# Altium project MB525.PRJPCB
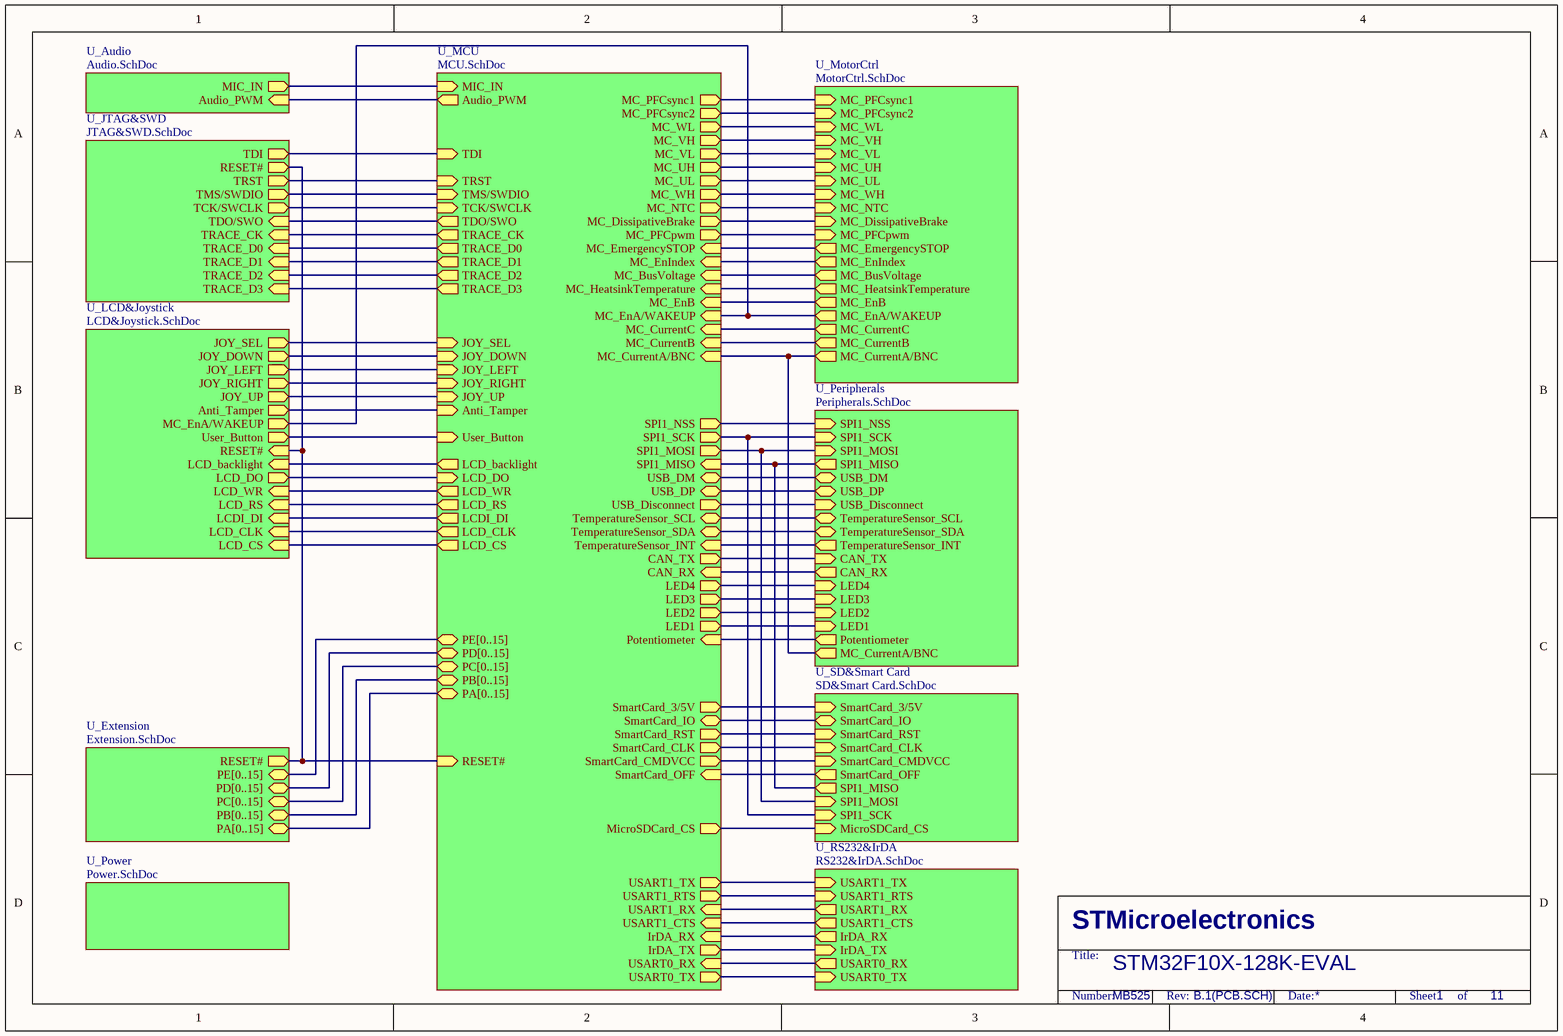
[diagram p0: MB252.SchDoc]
11 sheets, 281 parts. Net scope: hierarchical (ports join the sheet entries above them; power ports are global).
Board file: MB525.PCBDOC
Sheets:
  MB252.SchDoc
    U_MCU = MCU.SchDoc
    U_Audio = Audio.SchDoc
    U_Extension = Extension.SchDoc
    U_JTAG&SWD = JTAG&SWD.SchDoc
    U_LCD&Joystick = LCD&Joystick.SchDoc
    U_MotorCtrl = MotorCtrl.SchDoc
    U_Peripherals = Peripherals.SchDoc
    U_Power = Power.SchDoc
    U_RS232&IrDA = RS232&IrDA.SchDoc
    U_SD&Smart Card = SD&Smart Card.SchDoc

## Sheet MB252.SchDoc
size A4; Revision: B.1(PCB.SCH)

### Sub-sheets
U_Audio = Audio.SchDoc: Audio_PWM (in), MIC_IN (out)
U_Extension = Extension.SchDoc: PA[0..15] (bidir), PB[0..15] (bidir), PC[0..15] (bidir), PD[0..15] (bidir), PE[0..15] (bidir), RESET# (out)
U_JTAG&SWD = JTAG&SWD.SchDoc: TDI (out), RESET# (out), TRACE_D3 (in), TRACE_D2 (in), TRACE_D1 (in), TRACE_D0 (in), TRACE_CK (in), TRST (out), TMS/SWDIO (out), TCK/SWCLK (out), TDO/SWO (in)
U_LCD&Joystick = LCD&Joystick.SchDoc: JOY_SEL (out), JOY_DOWN (out), JOY_LEFT (out), JOY_RIGHT (out), JOY_UP (out), LCD_CS (in), LCD_CLK (in), LCD_DO (out), LCDI_DI (in), LCD_RS (in), LCD_WR (in), RESET# (in), LCD_backlight (in), Anti_Tamper (out), MC_EnA/WAKEUP (out), User_Button (out)
U_MCU = MCU.SchDoc: MC_EnA/WAKEUP (in), MC_EnB (in), JOY_DOWN (in), MC_BusVoltage (in), SPI1_NSS (out), SPI1_SCK (out), SPI1_MISO (in), SPI1_MOSI (out), LCD_backlight (out), USART0_TX (out), USART0_RX (in), USB_DM (bidir), USB_DP (bidir), TMS/SWDIO (in), TCK/SWCLK (in), TDI (in), MC_PFCsync1 (out), MC_PFCpwm (out), TDO/SWO (out), TRST (in), TemperatureSensor_INT (in), TemperatureSensor_SCL (bidir), TemperatureSensor_SDA (bidir), Audio_PWM (out), User_Button (in), SmartCard_IO (bidir), SmartCard_RST (out), SmartCard_CLK (out), LCD_CLK (out), LCD_DO (in), LCDI_DI (out), LCD_CS (out), RESET# (in), LCD_WR (out), MC_EnIndex (in), MC_DissipativeBrake (out), JOY_SEL (in), SmartCard_3/5V (out), MC_NTC (out), USB_Disconnect (out), JOY_UP (in), USART1_RX (in), USART1_TX (out), USART1_RTS (out), USART1_CTS (in), MC_PFCsync2 (out), CAN_TX (out), CAN_RX (in), MC_EmergencySTOP (in), SmartCard_OFF (in), MC_WL (out), MC_VH (out), MC_VL (out), MC_UH (out), MC_UL (out), SmartCard_CMDVCC (out), TRACE_D3 (out), TRACE_D2 (out), TRACE_D1 (out), TRACE_D0 (out), TRACE_CK (out), JOY_LEFT (in), JOY_RIGHT (in), MC_WH (out), LCD_RS (out), Anti_Tamper (in), MicroSDCard_CS (out), IrDA_RX (in), IrDA_TX (out), LED4 (out), LED3 (out), LED1 (out), MIC_IN (in), Potentiometer (in), MC_CurrentC (in), MC_CurrentB (in), MC_CurrentA/BNC (in), MC_HeatsinkTemperature (in), LED2 (out), PA[0..15] (bidir), PB[0..15] (bidir), PC[0..15] (bidir), PD[0..15] (bidir), PE[0..15] (bidir)
U_MotorCtrl = MotorCtrl.SchDoc: MC_EmergencySTOP (out), MC_CurrentA/BNC (out), MC_CurrentB (out), MC_CurrentC (out), MC_PFCsync1 (in), MC_PFCsync2 (in), MC_WL (in), MC_VH (in), MC_VL (in), MC_UH (in), MC_UL (in), MC_WH (in), MC_NTC (in), MC_DissipativeBrake (in), MC_PFCpwm (in), MC_EnA/WAKEUP (out), MC_EnB (out), MC_HeatsinkTemperature (out), MC_BusVoltage (out), MC_EnIndex (out)
U_Peripherals = Peripherals.SchDoc: SPI1_NSS (in), SPI1_SCK (in), SPI1_MISO (out), SPI1_MOSI (in), LED4 (in), LED3 (in), LED1 (in), LED2 (in), USB_DM (bidir), USB_DP (bidir), USB_Disconnect (in), TemperatureSensor_INT (out), TemperatureSensor_SCL (bidir), TemperatureSensor_SDA (bidir), MC_CurrentA/BNC (out), CAN_TX (in), CAN_RX (out), Potentiometer (out)
U_Power = Power.SchDoc: no entries
U_RS232&IrDA = RS232&IrDA.SchDoc: USART1_RX (out), USART1_TX (in), USART1_RTS (in), USART1_CTS (out), USART0_TX (in), USART0_RX (out), IrDA_RX (out), IrDA_TX (in)
U_SD&Smart Card = SD&Smart Card.SchDoc: SmartCard_3/5V (in), SmartCard_IO (bidir), SmartCard_RST (in), SmartCard_CLK (in), SmartCard_OFF (out), SmartCard_CMDVCC (in), SPI1_SCK (in), SPI1_MISO (out), SPI1_MOSI (in), MicroSDCard_CS (in)

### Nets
PA0: sheet U_MCU/MC_EnA/WAKEUP, sheet U_LCD&Joystick/MC_EnA/WAKEUP, sheet U_MotorCtrl/MC_EnA/WAKEUP
PA1: sheet U_MCU/MC_EnB, sheet U_MotorCtrl/MC_EnB
PA2: sheet U_MCU/MC_EnIndex, sheet U_MotorCtrl/MC_EnIndex
PA3: sheet U_MCU/MC_BusVoltage, sheet U_MotorCtrl/MC_BusVoltage
PA4: sheet U_MCU/SPI1_NSS, sheet U_Peripherals/SPI1_NSS
PA5: sheet U_MCU/SPI1_SCK, sheet U_Peripherals/SPI1_SCK, sheet U_SD&Smart Card/SPI1_SCK
PA6: sheet U_MCU/SPI1_MISO, sheet U_Peripherals/SPI1_MISO, sheet U_SD&Smart Card/SPI1_MISO
PA7: sheet U_MCU/SPI1_MOSI, sheet U_Peripherals/SPI1_MOSI, sheet U_SD&Smart Card/SPI1_MOSI
PA8: sheet U_MCU/LCD_backlight, sheet U_LCD&Joystick/LCD_backlight
PA9: sheet U_MCU/USART0_TX, sheet U_RS232&IrDA/USART0_TX
PA10: sheet U_MCU/USART0_RX, sheet U_RS232&IrDA/USART0_RX
PA11: sheet U_MCU/USB_DM, sheet U_Peripherals/USB_DM
PA12: sheet U_MCU/USB_DP, sheet U_Peripherals/USB_DP
PA13: sheet U_MCU/TMS/SWDIO, sheet U_JTAG&SWD/TMS/SWDIO
PA14: sheet U_MCU/TCK/SWCLK, sheet U_JTAG&SWD/TCK/SWCLK
PA15: sheet U_MCU/TDI, sheet U_JTAG&SWD/TDI
PB0: sheet U_MCU/MC_PFCsync1, sheet U_MotorCtrl/MC_PFCsync1
PB1: sheet U_MCU/MC_PFCpwm, sheet U_MotorCtrl/MC_PFCpwm
PB2: sheet U_MCU/LCD_CS, sheet U_LCD&Joystick/LCD_CS
PB3: sheet U_MCU/TDO/SWO, sheet U_JTAG&SWD/TDO/SWO
PB4: sheet U_MCU/TRST, sheet U_JTAG&SWD/TRST
PB5: sheet U_MCU/TemperatureSensor_INT, sheet U_Peripherals/TemperatureSensor_INT
PB6: sheet U_MCU/TemperatureSensor_SCL, sheet U_Peripherals/TemperatureSensor_SCL
PB7: sheet U_MCU/TemperatureSensor_SDA, sheet U_Peripherals/TemperatureSensor_SDA
PB8: sheet U_MCU/Audio_PWM, sheet U_Audio/Audio_PWM
PB9: sheet U_MCU/User_Button, sheet U_LCD&Joystick/User_Button
PB10: sheet U_MCU/SmartCard_IO, sheet U_SD&Smart Card/SmartCard_IO
PB11: sheet U_MCU/SmartCard_RST, sheet U_SD&Smart Card/SmartCard_RST
PB12: sheet U_MCU/SmartCard_CLK, sheet U_SD&Smart Card/SmartCard_CLK
PB13: sheet U_MCU/LCD_CLK, sheet U_LCD&Joystick/LCD_CLK
PB14: sheet U_MCU/LCD_DO, sheet U_LCD&Joystick/LCD_DO
PB15: sheet U_MCU/LCDI_DI, sheet U_LCD&Joystick/LCDI_DI
PC0: sheet U_MCU/MC_HeatsinkTemperature, sheet U_MotorCtrl/MC_HeatsinkTemperature
PC1: sheet U_MCU/MC_CurrentA/BNC, sheet U_MotorCtrl/MC_CurrentA/BNC, sheet U_Peripherals/MC_CurrentA/BNC
PC2: sheet U_MCU/MC_CurrentB, sheet U_MotorCtrl/MC_CurrentB
PC3: sheet U_MCU/MC_CurrentC, sheet U_MotorCtrl/MC_CurrentC
PC4: sheet U_MCU/Potentiometer, sheet U_Peripherals/Potentiometer
PC5: sheet U_MCU/MIC_IN, sheet U_Audio/MIC_IN
PC6: sheet U_MCU/LED1, sheet U_Peripherals/LED1
PC7: sheet U_MCU/LED2, sheet U_Peripherals/LED2
PC8: sheet U_MCU/LED3, sheet U_Peripherals/LED3
PC9: sheet U_MCU/LED4, sheet U_Peripherals/LED4
PC10: sheet U_MCU/IrDA_TX, sheet U_RS232&IrDA/IrDA_TX
PC11: sheet U_MCU/IrDA_RX, sheet U_RS232&IrDA/IrDA_RX
PC12: sheet U_MCU/MicroSDCard_CS, sheet U_SD&Smart Card/MicroSDCard_CS
PC13: sheet U_MCU/Anti_Tamper, sheet U_LCD&Joystick/Anti_Tamper
PD0: sheet U_MCU/CAN_RX, sheet U_Peripherals/CAN_RX
PD1: sheet U_MCU/CAN_TX, sheet U_Peripherals/CAN_TX
PD2: sheet U_MCU/MC_PFCsync2, sheet U_MotorCtrl/MC_PFCsync2
PD3: sheet U_MCU/USART1_CTS, sheet U_RS232&IrDA/USART1_CTS
PD4: sheet U_MCU/USART1_RTS, sheet U_RS232&IrDA/USART1_RTS
PD5: sheet U_MCU/USART1_TX, sheet U_RS232&IrDA/USART1_TX
PD6: sheet U_MCU/USART1_RX, sheet U_RS232&IrDA/USART1_RX
PD7: sheet U_MCU/LCD_RS, sheet U_LCD&Joystick/LCD_RS
PD8: sheet U_MCU/JOY_UP, sheet U_LCD&Joystick/JOY_UP
PD9: sheet U_MCU/USB_Disconnect, sheet U_Peripherals/USB_Disconnect
PD10: sheet U_MCU/MC_NTC, sheet U_MotorCtrl/MC_NTC
PD11: sheet U_MCU/SmartCard_3/5V, sheet U_SD&Smart Card/SmartCard_3/5V
PD12: sheet U_MCU/JOY_SEL, sheet U_LCD&Joystick/JOY_SEL
PD13: sheet U_MCU/MC_DissipativeBrake, sheet U_MotorCtrl/MC_DissipativeBrake
PD14: sheet U_MCU/JOY_DOWN, sheet U_LCD&Joystick/JOY_DOWN
PD15: sheet U_MCU/LCD_WR, sheet U_LCD&Joystick/LCD_WR
PE0: sheet U_MCU/JOY_RIGHT, sheet U_LCD&Joystick/JOY_RIGHT
PE1: sheet U_MCU/JOY_LEFT, sheet U_LCD&Joystick/JOY_LEFT
PE2: sheet U_MCU/TRACE_CK, sheet U_JTAG&SWD/TRACE_CK
PE3: sheet U_MCU/TRACE_D0, sheet U_JTAG&SWD/TRACE_D0
PE4: sheet U_MCU/TRACE_D1, sheet U_JTAG&SWD/TRACE_D1
PE5: sheet U_MCU/TRACE_D2, sheet U_JTAG&SWD/TRACE_D2
PE6: sheet U_MCU/TRACE_D3, sheet U_JTAG&SWD/TRACE_D3
PE7: sheet U_MCU/SmartCard_CMDVCC, sheet U_SD&Smart Card/SmartCard_CMDVCC
PE8: sheet U_MCU/MC_UL, sheet U_MotorCtrl/MC_UL
PE9: sheet U_MCU/MC_UH, sheet U_MotorCtrl/MC_UH
PE10: sheet U_MCU/MC_VL, sheet U_MotorCtrl/MC_VL
PE11: sheet U_MCU/MC_VH, sheet U_MotorCtrl/MC_VH
PE12: sheet U_MCU/MC_WL, sheet U_MotorCtrl/MC_WL
PE13: sheet U_MCU/MC_WH, sheet U_MotorCtrl/MC_WH
PE14: sheet U_MCU/SmartCard_OFF, sheet U_SD&Smart Card/SmartCard_OFF
PE15: sheet U_MCU/MC_EmergencySTOP, sheet U_MotorCtrl/MC_EmergencySTOP
RESET#: sheet U_MCU/RESET#, sheet U_Extension/RESET#, sheet U_JTAG&SWD/RESET#, sheet U_LCD&Joystick/RESET#

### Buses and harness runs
bus sheet U_Extension/PA[0..15] = sheet U_MCU/PA[0..15]
bus sheet U_Extension/PB[0..15] = sheet U_MCU/PB[0..15]
bus sheet U_Extension/PC[0..15] = sheet U_MCU/PC[0..15]
bus sheet U_Extension/PD[0..15] = sheet U_MCU/PD[0..15]
bus sheet U_Extension/PE[0..15] = sheet U_MCU/PE[0..15]

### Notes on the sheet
- STM32F10X-128K-EVAL
- MB525
- 1
- 11

## Sheet MCU.SchDoc
size A4; Revision: B.1(PCB.SCH)
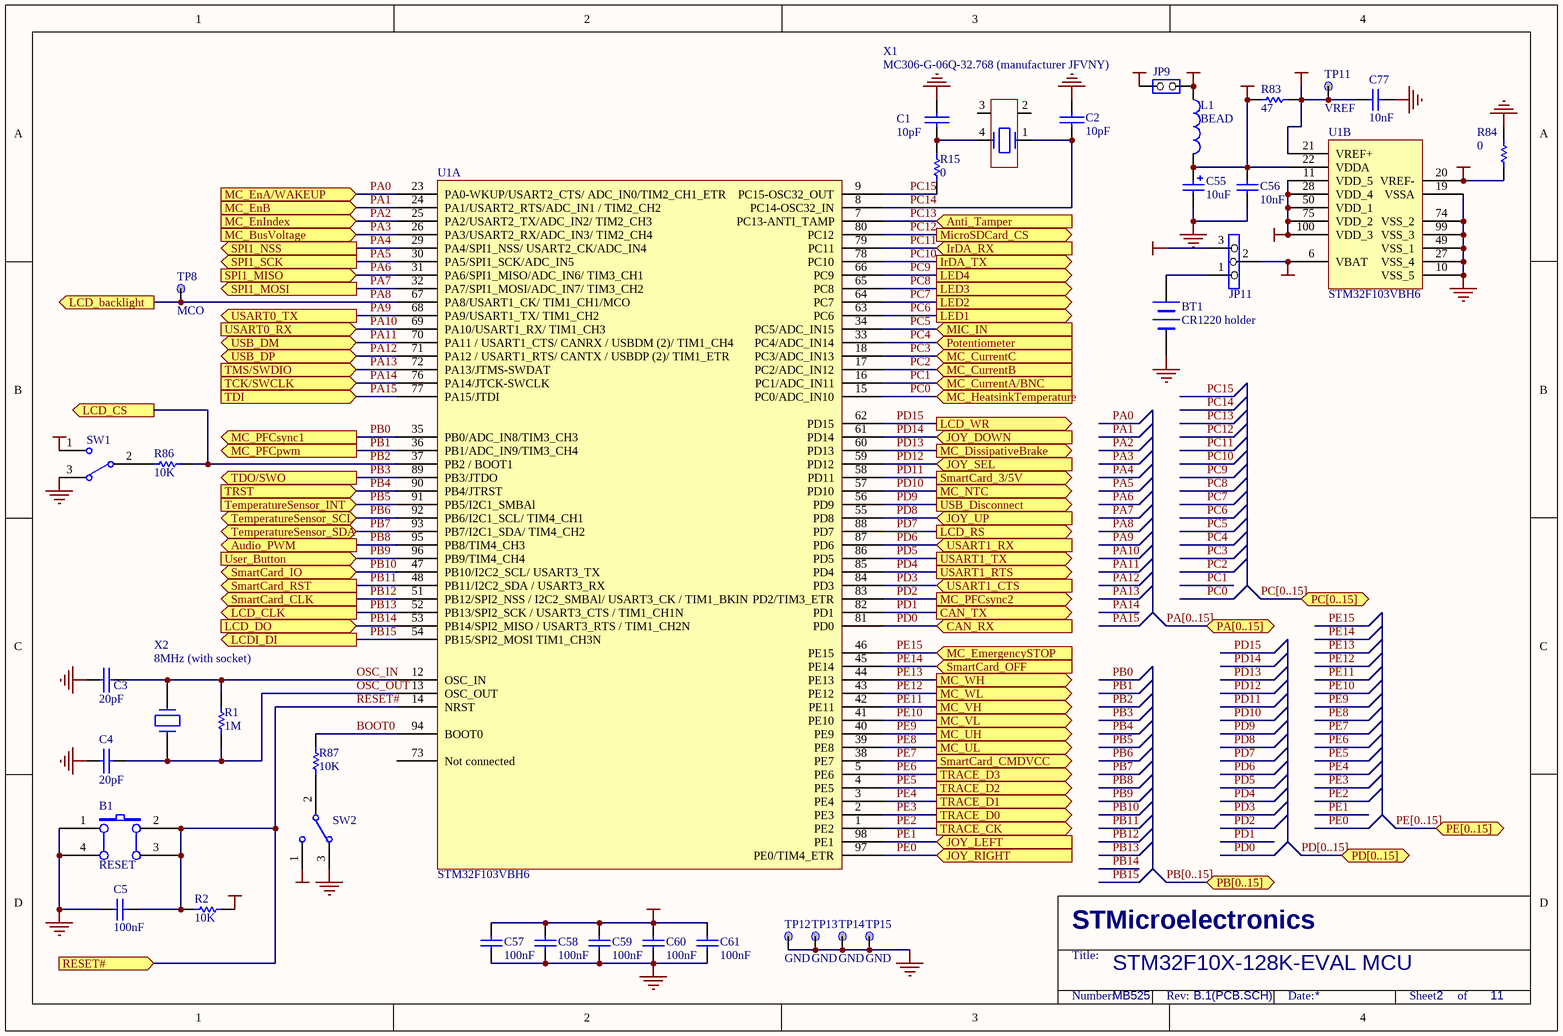
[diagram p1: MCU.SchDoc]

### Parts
B1  RESET  [PB10]
BT1  CR1220 holder  [BATT]
C1  10pF  [0603]
C2  10pF  [0603]
C3  20pF  [0603]
C4  20pF  [0603]
C5  100nF  [0603P]
C55  10uF  [TAN-B]
C56  10nF  [0603]
C57  100nF  [0603P]
C58  100nF  [0603P]
C59  100nF  [0603P]
C60  100nF  [0603P]
C61  100nF  [0603P]
C77  10nF  [0603]
JP9  (no value)  [SIP2]
JP11  (no value)  [SIP3]
L1  BEAD  [0603]
R1  1M  [0603]
R2  10K  [0603]
R15  0  [0805]
R83  47  [0805]
R84  0  [0805]
R86  10K  [0603]
R87  10K  [0603]
SW1  (no value)  [SIP3]
SW2  (no value)  [SIP3]
TP8  MCO  [TP]
TP11  VREF  [TP]
TP12  GND  [TP]
TP13  GND  [TP]
TP14  GND  [TP]
TP15  GND  [TP]
U1  STM32F103VBH6  (parts A,B of 2)
X1  MC306-G-06Q-32.768 (manufacturer JFVNY)  [SM8]
X2  8MHz (with socket)  [XTAL1]

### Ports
Anti_Tamper (in), Audio_PWM (out), CAN_RX (in), CAN_TX (out), IrDA_RX (in), IrDA_TX (out), JOY_DOWN (in), JOY_LEFT (in), JOY_RIGHT (in), JOY_SEL (in), JOY_UP (in), LCD_backlight (out), LCD_CLK (out), LCD_CS (out), LCD_DO (in), LCD_RS (out), LCD_WR (out), LCDI_DI (out), LED1 (out), LED2 (out), LED3 (out), LED4 (out), MC_BusVoltage (in), MC_CurrentA/BNC (in), MC_CurrentB (in), MC_CurrentC (in), MC_DissipativeBrake (out), MC_EmergencySTOP (in), MC_EnA/WAKEUP (in), MC_EnB (in), MC_EnIndex (in), MC_HeatsinkTemperature (in), MC_NTC (out), MC_PFCpwm (out), MC_PFCsync1 (out), MC_PFCsync2 (out), MC_UH (out), MC_UL (out), MC_VH (out), MC_VL (out), MC_WH (out), MC_WL (out), MIC_IN (in), MicroSDCard_CS (out), PA[0..15] (bidir), PB[0..15] (bidir), PC[0..15] (bidir), PD[0..15] (bidir), PE[0..15] (bidir), Potentiometer (in), RESET# (in), SmartCard_3/5V (out), SmartCard_CLK (out), SmartCard_CMDVCC (out), SmartCard_IO (bidir), SmartCard_OFF (in), SmartCard_RST (out), SPI1_MISO (in), SPI1_MOSI (out), SPI1_NSS (out), SPI1_SCK (out), TCK/SWCLK (in), TDI (in), TDO/SWO (out), TemperatureSensor_INT (in), TemperatureSensor_SCL (bidir), TemperatureSensor_SDA (bidir), TMS/SWDIO (in), TRACE_CK (out), TRACE_D0 (out), TRACE_D1 (out), TRACE_D2 (out), TRACE_D3 (out), TRST (in), USART0_RX (in), USART0_TX (out), USART1_CTS (in), USART1_RTS (out), USART1_RX (in), USART1_TX (out), USB_Disconnect (out), USB_DM (bidir), USB_DP (bidir), User_Button (in)

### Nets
+3V3: JP9.1(COMMON) JP11.3 R2.2 SW1.1 SW2.1
GND: B1.1(A0) B1.4(A1) BT1.2(-) C1.2 C2.2 C3.2 C4.2 C5.1 C55.2 C56.2 C57.2 C58.2 C59.2 C60.2 C61.2 C77.2 R84.1 SW1.3 SW2.3 TP12.1 TP13.1 TP14.1 TP15.1 U1.10(VSS_5) U1.19(VSSA) U1.27(VSS_4) U1.49(VSS_1) U1.74(VSS_2) U1.99(VSS_3)
Vbat: JP11.2 U1.6(VBAT)
VDD: C57.1 C58.1 C59.1 C60.1 C61.1 JP9.2(NO) L1.1 U1.11(VDD_5) U1.28(VDD_4) U1.50(VDD_1) U1.75(VDD_2) U1.100(VDD_3)
VDDA: C55.1 C56.1 L1.2 R83.2 U1.22(VDDA)
VREF+: C77.1 R83.1 TP11.1 U1.21(VREF+)
VREF-: R84.2 U1.20(VREF-)
BOOT0: R87.1 U1.94(BOOT0)
OSC_IN: C3.1 R1.2 U1.12(OSC_IN) X2.2
OSC_OUT: C4.1 R1.1 U1.13(OSC_OUT) X2.1
PA0: U1.23(PA0-WKUP/USART2_CTS/
ADC_IN0/TIM2_CH1_ETR) ; port MC_EnA/WAKEUP
PA1: U1.24(PA1/USART2_RTS/ADC_IN1
/
TIM2_CH2) ; port MC_EnB
PA2: U1.25(PA2/USART2_TX/ADC_IN2/
TIM2_CH3) ; port MC_EnIndex
PA3: U1.26(PA3/USART2_RX/ADC_IN3/
TIM2_CH4) ; port MC_BusVoltage
PA4: U1.29(PA4/SPI1_NSS/
USART2_CK/ADC_IN4) ; port SPI1_NSS
PA5: U1.30(PA5/SPI1_SCK/ADC_IN5) ; port SPI1_SCK
PA6: U1.31(PA6/SPI1_MISO/ADC_IN6/
TIM3_CH1) ; port SPI1_MISO
PA7: U1.32(PA7/SPI1_MOSI/ADC_IN7/
TIM3_CH2) ; port SPI1_MOSI
PA8: TP8.1 U1.67(PA8/USART1_CK/
TIM1_CH1/MCO) ; port LCD_backlight
PA9: U1.68(PA9/USART1_TX/
TIM1_CH2) ; port USART0_TX
PA10: U1.69(PA10/USART1_RX/
TIM1_CH3) ; port USART0_RX
PA11: U1.70(PA11_/_USART1_CTS/
CANRX_/_USBDM_(2)/
TIM1_CH4) ; port USB_DM
PA12: U1.71(PA12_/_USART1_RTS/
CANTX_/_USBDP_(2)/
TIM1_ETR) ; port USB_DP
PA13: U1.72(PA13/JTMS-SWDAT) ; port TMS/SWDIO
PA14: U1.76(PA14/JTCK-SWCLK) ; port TCK/SWCLK
PA15: U1.77(PA15/JTDI) ; port TDI
PB0: U1.35(PB0/ADC_IN8/TIM3_CH3) ; port MC_PFCsync1
PB1: U1.36(PB1/ADC_IN9/TIM3_CH4) ; port MC_PFCpwm
PB2: R86.1 U1.37(PB2_/_BOOT1) ; port LCD_CS
PB3: U1.89(PB3/JTDO) ; port TDO/SWO
PB4: U1.90(PB4/JTRST) ; port TRST
PB5: U1.91(PB5/I2C1_SMBAl) ; port TemperatureSensor_INT
PB6: U1.92(PB6/I2C1_SCL/
TIM4_CH1) ; port TemperatureSensor_SCL
PB7: U1.93(PB7/I2C1_SDA/
TIM4_CH2) ; port TemperatureSensor_SDA
PB8: U1.95(PB8/TIM4_CH3) ; port Audio_PWM
PB9: U1.96(PB9/TIM4_CH4) ; port User_Button
PB10: U1.47(PB10/I2C2_SCL/
USART3_TX) ; port SmartCard_IO
PB11: U1.48(PB11/I2C2_SDA_/
USART3_RX) ; port SmartCard_RST
PB12: U1.51(PB12/SPI2_NSS_/
I2C2_SMBAl/
USART3_CK_/
TIM1_BKIN) ; port SmartCard_CLK
PB13: U1.52(PB13/SPI2_SCK_/
USART3_CTS_/
TIM1_CH1N) ; port LCD_CLK
PB14: U1.53(PB14/SPI2_MISO_/
USART3_RTS_/
TIM1_CH2N) ; port LCD_DO
PB15: U1.54(PB15/SPI2_MOSI
TIM1_CH3N) ; port LCDI_DI
PC0: U1.15(PC0/ADC_IN10) ; port MC_HeatsinkTemperature
PC1: U1.16(PC1/ADC_IN11) ; port MC_CurrentA/BNC
PC2: U1.17(PC2/ADC_IN12) ; port MC_CurrentB
PC3: U1.18(PC3/ADC_IN13) ; port MC_CurrentC
PC4: U1.33(PC4/ADC_IN14) ; port Potentiometer
PC5: U1.34(PC5/ADC_IN15) ; port MIC_IN
PC6: U1.63(PC6) ; port LED1
PC7: U1.64(PC7) ; port LED2
PC8: U1.65(PC8) ; port LED3
PC9: U1.66(PC9) ; port LED4
PC10: U1.78(PC10) ; port IrDA_TX
PC11: U1.79(PC11) ; port IrDA_RX
PC12: U1.80(PC12) ; port MicroSDCard_CS
PC13: U1.7(PC13-ANTI_TAMP) ; port Anti_Tamper
PC14: C2.1 U1.8(PC14-OSC32_IN) X1.1
PC15: R15.2 U1.9(PC15-OSC32_OUT)
PD0: U1.81(PD0) ; port CAN_RX
PD1: U1.82(PD1) ; port CAN_TX
PD2: U1.83(PD2/TIM3_ETR) ; port MC_PFCsync2
PD3: U1.84(PD3) ; port USART1_CTS
PD4: U1.85(PD4) ; port USART1_RTS
PD5: U1.86(PD5) ; port USART1_TX
PD6: U1.87(PD6) ; port USART1_RX
PD7: U1.88(PD7) ; port LCD_RS
PD8: U1.55(PD8) ; port JOY_UP
PD9: U1.56(PD9) ; port USB_Disconnect
PD10: U1.57(PD10) ; port MC_NTC
PD11: U1.58(PD11) ; port SmartCard_3/5V
PD12: U1.59(PD12) ; port JOY_SEL
PD13: U1.60(PD13) ; port MC_DissipativeBrake
PD14: U1.61(PD14) ; port JOY_DOWN
PD15: U1.62(PD15) ; port LCD_WR
PE0: U1.97(PE0/TIM4_ETR) ; port JOY_RIGHT
PE1: U1.98(PE1) ; port JOY_LEFT
PE2: U1.1(PE2) ; port TRACE_CK
PE3: U1.2(PE3) ; port TRACE_D0
PE4: U1.3(PE4) ; port TRACE_D1
PE5: U1.4(PE5) ; port TRACE_D2
PE6: U1.5(PE6) ; port TRACE_D3
PE7: U1.38(PE7) ; port SmartCard_CMDVCC
PE8: U1.39(PE8) ; port MC_UL
PE9: U1.40(PE9) ; port MC_UH
PE10: U1.41(PE10) ; port MC_VL
PE11: U1.42(PE11) ; port MC_VH
PE12: U1.43(PE12) ; port MC_WL
PE13: U1.44(PE13) ; port MC_WH
PE14: U1.45(PE14) ; port SmartCard_OFF
PE15: U1.46(PE15) ; port MC_EmergencySTOP
RESET#: B1.2(B0) B1.3(B1) C5.2 R2.1 U1.14(NRST) ; port RESET#
NetBT1_1: BT1.1(+) JP11.1
NetC1_1: C1.1 R15.1 X1.4
NetR86_2: R86.2 SW1.2
NetR87_2: R87.2 SW2.2

Not connected (* = marked no-connect by the designer): U1 73(Not_connected); X1 2 3

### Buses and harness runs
bus PA[0..15] = port PA[0..15]
bus PB[0..15] = port PB[0..15]
bus PC[0..15] = port PC[0..15]
bus PD[0..15] = port PD[0..15]
bus PE[0..15] = port PE[0..15]

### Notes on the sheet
- STM32F10X-128K-EVAL MCU
- MB525
- 2
- 11

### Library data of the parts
B1 = SW PUSHBUTTON: SE PUSHBUTTON
BT1 = BATTERY
C1-C4 C57-C61 = CAP: Capacitor
C5 = CAP: Capacitor; Value: 100pF
C55 = Cap Pol1: Polarized Capacitor (Radial)
C56 C77 = Cap: Capacitor
JP9 = JP2
JP11 = Jumper3
L1 = Inductor: Value: 100uH
R1 R15 R83 R84 = Res1: Resistor; Value: 1K
R2 R86 R87 = res1: Resistor; Value: 1K
SW1 SW2 = SW-SPDT: SPDT Subminiature Toggle Switch, Right Angle Mounting, Vertical Actuation; Revision 1: Jul-2002: Re-released for DXP Platform.; Revision 2: 17-Dec-2003: Schematic revised, PCB Footprint replaced.
TP8 TP11-TP15 = TP
X1 = MC306
X2 = CRYSTAL

## Sheet Audio.SchDoc
size A4; Revision: B.1(PCB.SCH)
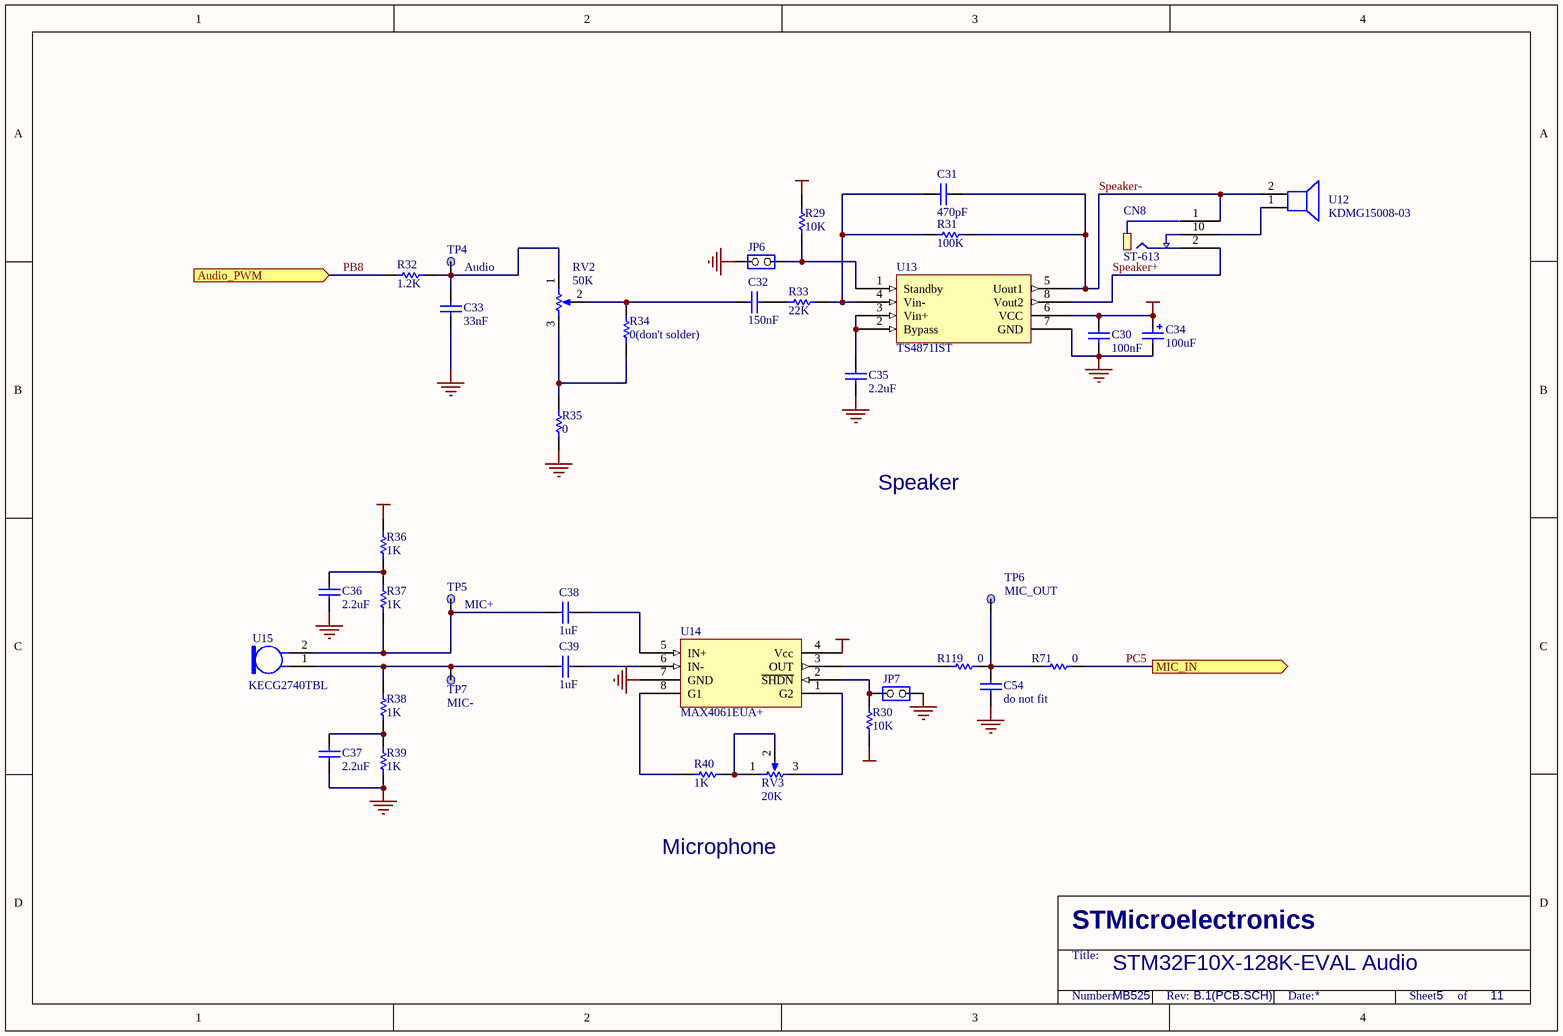
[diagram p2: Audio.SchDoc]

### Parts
C30  100nF  [0603P]
C31  470pF  [0603]
C32  150nF  [0603]
C33  33nF  [0603]
C34  100uF  [TAN-B]
C35  2.2uF  [0805]
C36  2.2uF  [0805]
C37  2.2uF  [0805]
C38  1uF  [0603]
C39  1uF  [0603]
C54  do not fit  [0603]
CN8  ST-613  [PJST-613]
JP6  (no value)  [SIP2]
JP7  (no value)  [SIP2]
R29  10K  [0603]
R30  10K  [0603]
R31  100K  [0603]
R32  1.2K  [0603]
R33  22K  [0603]
R34  0(don't solder)  [0603]
R35  0  [0603]
R36  1K  [0603]
R37  1K  [0603]
R38  1K  [0603]
R39  1K  [0603]
R40  1K  [0603]
R71  0  [0805]
R119  0  [0603]
RV2  50K  [3314-J]
RV3  20K  [3314-J]
TP4  Audio  [TP]
TP5  MIC+  [TP]
TP6  MIC_OUT  [TP]
TP7  MIC-  [TP]
U12  KDMG15008-03  [KS1508]
U13  TS4871IST  [TSSOP8]
U14  MAX4061EUA+  [tssop8]
U15  KECG2740TBL  [KEC2740]

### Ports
Audio_PWM (in), MIC_IN (out)

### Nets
+3V3: C30.2 C34.1 R29.2 R30.1 R36.2 U13.6(VCC) U14.4(Vcc)
GND: C30.1 C33.1 C34.2 C35.2 C36.2 C37.2 C54.2 JP6.2(NO) JP7.2(NO) R35.1 R39.1 U13.7(GND) U14.7(GND)
PB8: R32.1 ; port Audio_PWM
PC5: R71.1 ; port MIC_IN
Speaker+: CN8.2 U13.8(Vout2)
Speaker-: C31.2 CN8.1 R31.2 U12.2(--) U13.5(Uout1)
NetC31_1: C31.1 R31.1 R33.2 U13.4(Vin-)
NetC32_1: C32.1 R34.2 RV2.2(TAP)
NetC32_2: C32.2 R33.1
NetC33_2: C33.2 R32.2 RV2.1(BOT) TP4.1
NetC35_1: C35.1 U13.2(Bypass) U13.3(Vin+)
NetC36_1: C36.1 R36.1 R37.1
NetC37_1: C37.1 R38.1 R39.2
NetC38_1: C38.1 R37.2 TP5.1 U15.2
NetC38_2: C38.2 U14.5(IN+)
NetC39_1: C39.1 R38.2 TP7.1 U15.1
NetC39_2: C39.2 U14.6(IN-)
NetC54_1: C54.1 R71.2 R119.1 TP6.1
NetCN8_10: CN8.10 U12.1(+)
NetJP6_1: JP6.1(COMMON) R29.1 U13.1(Standby)
NetJP7_1: JP7.1(COMMON) R30.2 U14.2(~{SHDN})
NetR34_1: R34.1 R35.2 RV2.3(TOP)
NetR40_1: R40.1 RV3.1(BOT) RV3.2(TAP)
NetR40_2: R40.2 U14.8(G1)
NetR119_2: R119.2 U14.3(OUT)
NetRV3_3: RV3.3(TOP) U14.1(G2)

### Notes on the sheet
- Speaker
- Microphone
- STM32F10X-128K-EVAL Audio
- MB525
- 5
- 11

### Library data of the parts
C30-C33 C35-C39 = CAP: Capacitor; Value: 100pF
C34 = Cap Pol1: Polarized Capacitor (Radial); Value: 100pF
C54 = CAP: Capacitor; Value: 100nF
JP6 JP7 = JP2
R29-R35 R71 R119 = Res1: Resistor; Value: 1K
R36-R40 = Res1: Resistor
RV2 RV3 = RV
TP4-TP7 = TP
U12 = Speaker: Loudspeaker
U15 = Mic2: Microphone

## Sheet Extension.SchDoc
size A4; Revision: B.1(PCB.SCH)
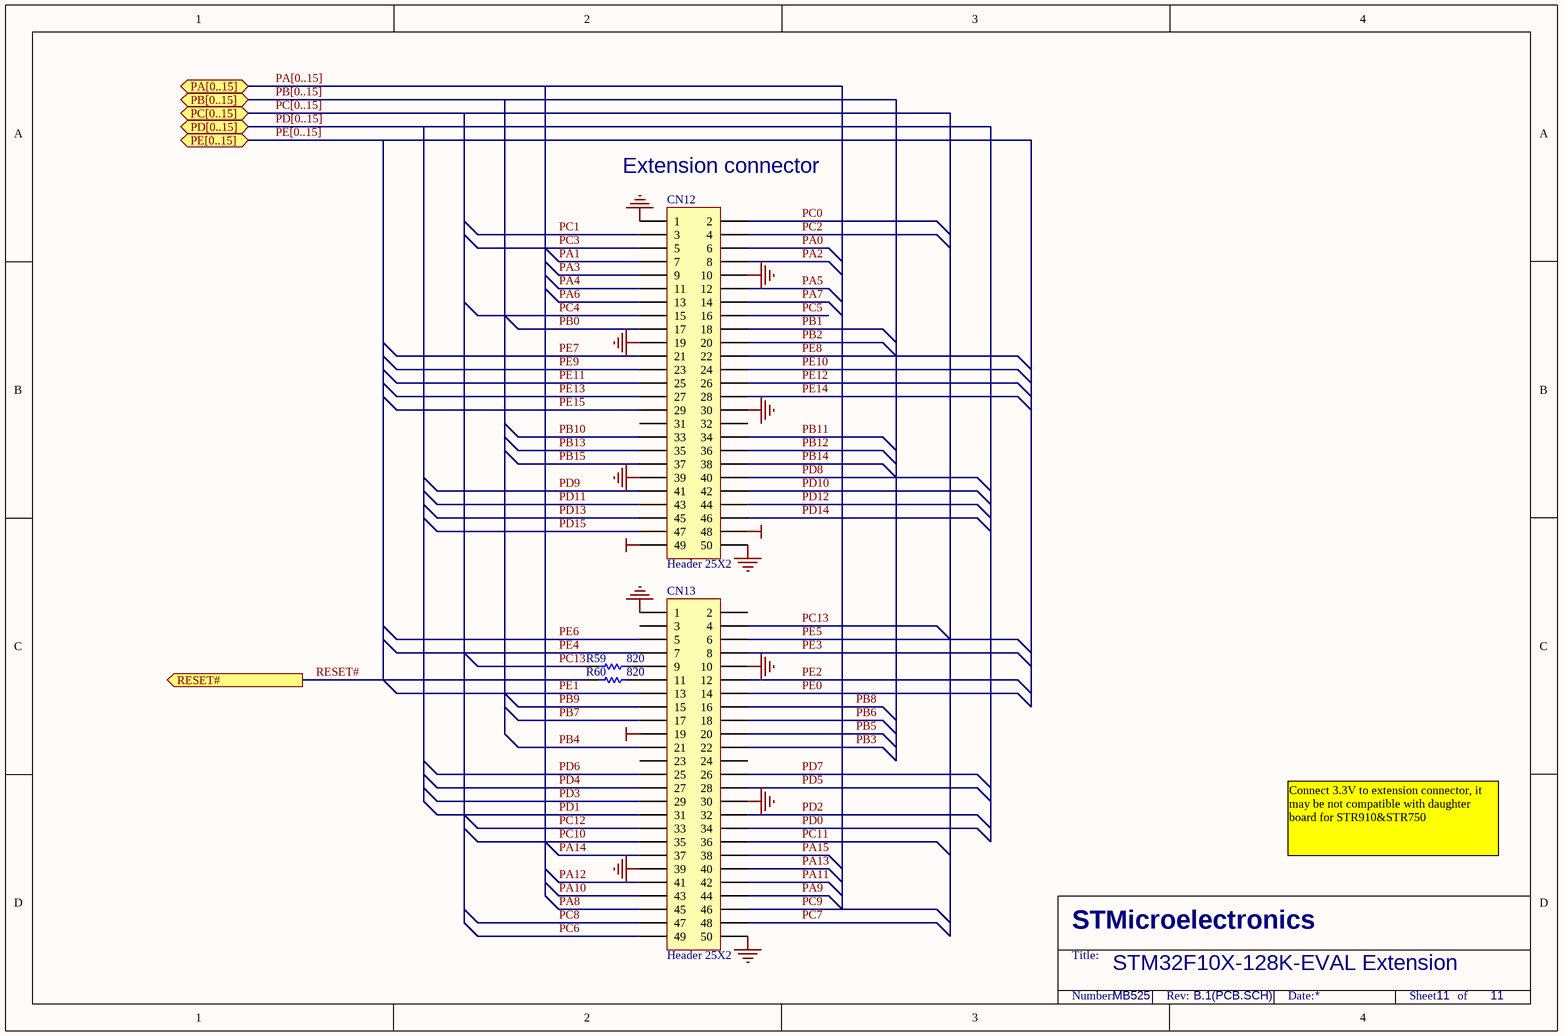
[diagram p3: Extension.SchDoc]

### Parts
CN12  Header 25X2  [2*25P]
CN13  Header 25X2  [2*25P]
R59  820  [0603]
R60  820  [0603]

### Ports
PA[0..15] (bidir), PB[0..15] (bidir), PC[0..15] (bidir), PD[0..15] (bidir), PE[0..15] (bidir), RESET# (out)

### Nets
+3V3: CN12.48
D5V: CN12.49 CN13.19
GND: CN12.1 CN12.10 CN12.19 CN12.30 CN12.39 CN12.50 CN13.1 CN13.10 CN13.30 CN13.39 CN13.50
PA0: CN12.6
PA1: CN12.7
PA2: CN12.8
PA3: CN12.9
PA4: CN12.11
PA5: CN12.12
PA6: CN12.13
PA7: CN12.14
PA8: CN13.45
PA9: CN13.44
PA10: CN13.43
PA11: CN13.42
PA12: CN13.41
PA13: CN13.40
PA14: CN13.37
PA15: CN13.38
PB0: CN12.17
PB1: CN12.18
PB2: CN12.20
PB3: CN13.22
PB4: CN13.21
PB5: CN13.20
PB6: CN13.18
PB7: CN13.17
PB8: CN13.16
PB9: CN13.15
PB10: CN12.33
PB11: CN12.34
PB12: CN12.36
PB13: CN12.35
PB14: CN12.38
PB15: CN12.37
PC0: CN12.2
PC1: CN12.3
PC2: CN12.4
PC3: CN12.5
PC4: CN12.15
PC5: CN12.16
PC6: CN13.49
PC7: CN13.48
PC8: CN13.47
PC9: CN13.46
PC10: CN13.35
PC11: CN13.36
PC12: CN13.33
PC13: CN13.4 R59.1
PD0: CN13.34
PD1: CN13.31
PD2: CN13.32
PD3: CN13.29
PD4: CN13.27
PD5: CN13.28
PD6: CN13.25
PD7: CN13.26
PD8: CN12.40
PD9: CN12.41
PD10: CN12.42
PD11: CN12.43
PD12: CN12.44
PD13: CN12.45
PD14: CN12.46
PD15: CN12.47
PE0: CN13.14
PE1: CN13.13
PE2: CN13.12
PE3: CN13.8
PE4: CN13.7
PE5: CN13.6
PE6: CN13.5
PE7: CN12.21
PE8: CN12.22
PE9: CN12.23
PE10: CN12.24
PE11: CN12.25
PE12: CN12.26
PE13: CN12.27
PE14: CN12.28
PE15: CN12.29
RESET#: R60.2 ; port RESET#
NetCN13_9: CN13.9 R59.2
NetCN13_11: CN13.11 R60.1

Not connected (* = marked no-connect by the designer): CN12 31 32; CN13 2 3 23 24

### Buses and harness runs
bus PA[0..15] = port PA[0..15]
bus PB[0..15] = port PB[0..15]
bus PC[0..15] = port PC[0..15]
bus PD[0..15] = port PD[0..15]
bus PE[0..15] = port PE[0..15]

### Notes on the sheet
- (near CN12) Extension connector
- Connect 3.3V to extension connector, it may be not compatible with daughter board for STR910&STR750
- STM32F10X-128K-EVAL Extension
- MB525
- 11

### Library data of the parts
CN12 CN13 = Header 25X2: Header, 25-Pin, Dual row
R59 R60 = Res1: Resistor; Value: 1K

## Sheet JTAG&SWD.SchDoc
size A4; Revision: B.1(PCB.SCH)
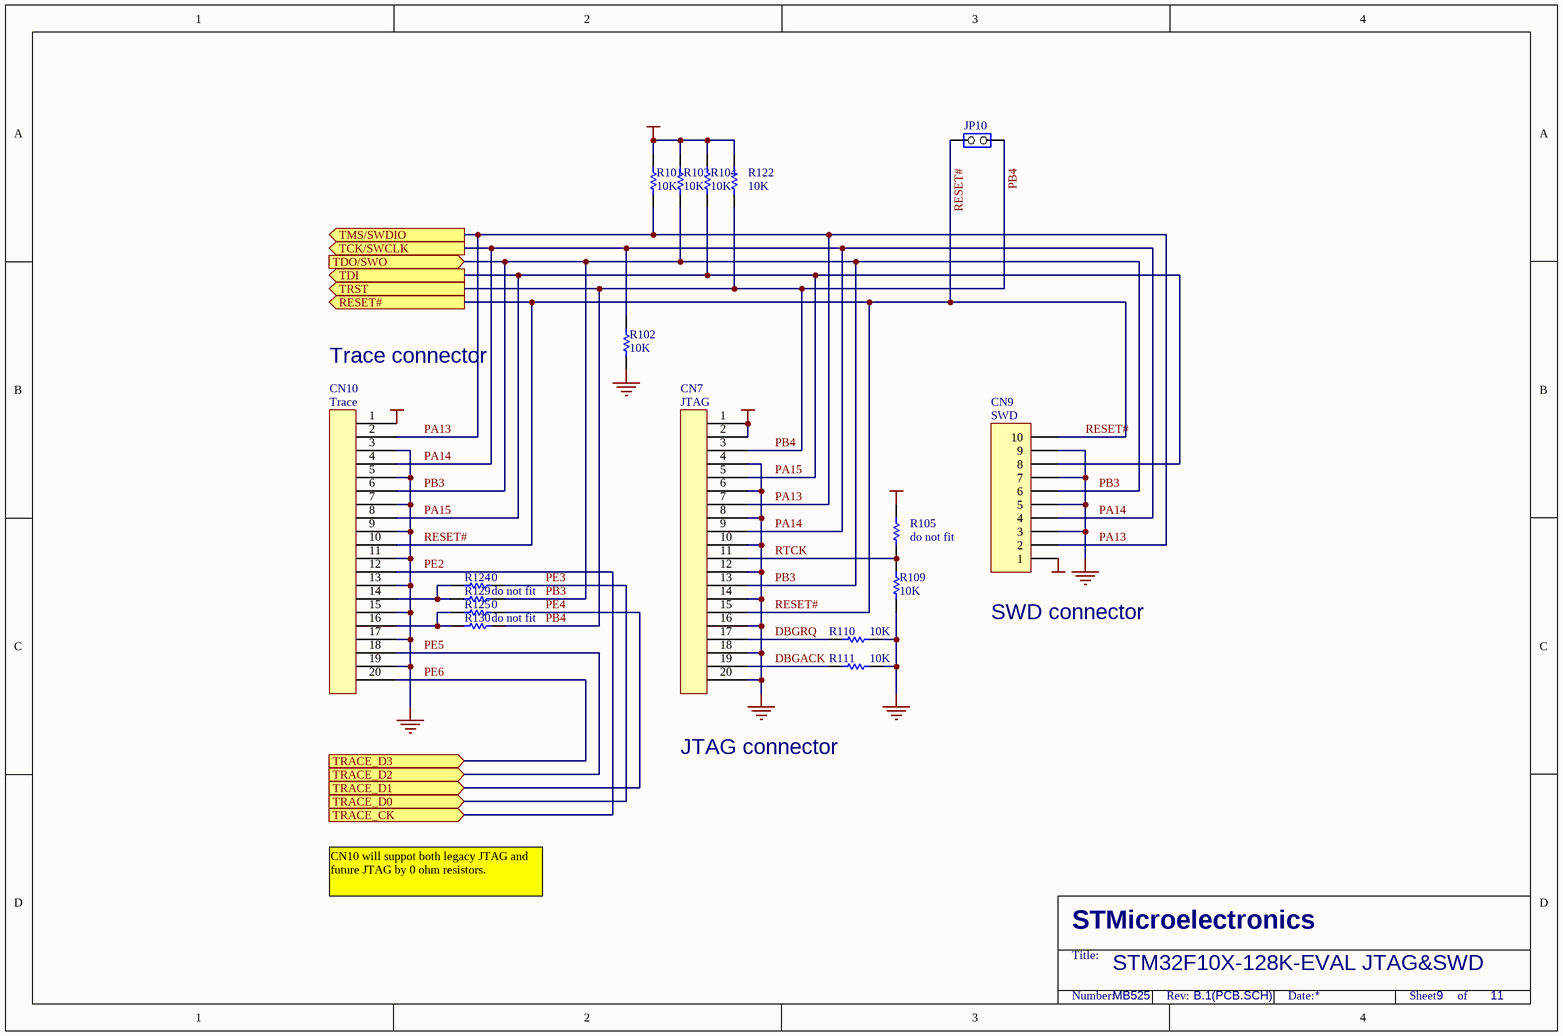
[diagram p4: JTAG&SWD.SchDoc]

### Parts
CN7  JTAG  [IDC20S]
CN9  SWD  [IDC10S]
CN10  Trace  [IDC20S]
JP10  (no value)  [SIP2]
R101  10K  [0603]
R102  10K  [0603]
R103  10K  [0603]
R104  10K  [0603]
R105  do not fit  [0603]
R109  10K  [0603]
R110  10K  [0603]
R111  10K  [0603]
R122  10K  [0603]
R124  0  [0603]
R125  0  [0603]
R129  do not fit  [0603]
R130  do not fit  [0603]

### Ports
RESET# (out), TCK/SWCLK (out), TDI (out), TDO/SWO (in), TMS/SWDIO (out), TRACE_CK (in), TRACE_D0 (in), TRACE_D1 (in), TRACE_D2 (in), TRACE_D3 (in), TRST (out)

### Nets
+3V3: CN7.1 CN7.2 CN9.1 CN10.1 R101.2 R103.2 R104.2 R105.2 R122.2
GND: CN7.4 CN7.6 CN7.8 CN7.10 CN7.12 CN7.14 CN7.16 CN7.18 CN7.20 CN9.3 CN9.5 CN9.7 CN9.9 CN10.3 CN10.5 CN10.7 CN10.9 CN10.11 CN10.13 CN10.15 CN10.17 CN10.19 R102.1 R109.1 R110.2 R111.2
DBGACK: CN7.19 R111.1
DBGRQ: CN7.17 R110.1
PA13: CN7.7 CN9.2 CN10.2 R101.1 ; port TMS/SWDIO
PA14: CN7.9 CN9.4 CN10.4 R102.2 ; port TCK/SWCLK
PA15: CN7.5 CN9.8 CN10.8 R104.1 ; port TDI
PB3: CN7.13 CN9.6 CN10.6 R103.1 R129.2 ; port TDO/SWO
PB4: CN7.3 JP10.1(COMMON) R122.1 R130.2 ; port TRST
PE2: CN10.12 ; port TRACE_CK
PE3: R124.2 ; port TRACE_D0
PE4: R125.2 ; port TRACE_D1
PE5: CN10.18 ; port TRACE_D2
PE6: CN10.20 ; port TRACE_D3
RESET#: CN7.15 CN9.10 CN10.10 JP10.2(NO) ; port RESET#
RTCK: CN7.11 R105.1 R109.2
NetCN10_14: CN10.14 R124.1 R129.1
NetCN10_16: CN10.16 R125.1 R130.1

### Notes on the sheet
- Trace connector
- (near CN9) SWD connector
- JTAG connector
- CN10 will suppot both legacy JTAG and future JTAG by 0 ohm resistors.
- STM32F10X-128K-EVAL JTAG&SWD
- MB525
- 9
- 11

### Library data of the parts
CN7 CN10 = 20PIN1
CN9 = Header 10: Header, 10-Pin
JP10 = JP2
R101-R105 R109-R111 R122 R124 R125 R129 R130 = Res1: Resistor; Value: 1K

## Sheet LCD&Joystick.SchDoc
size A4; Revision: B.1(PCB.SCH)
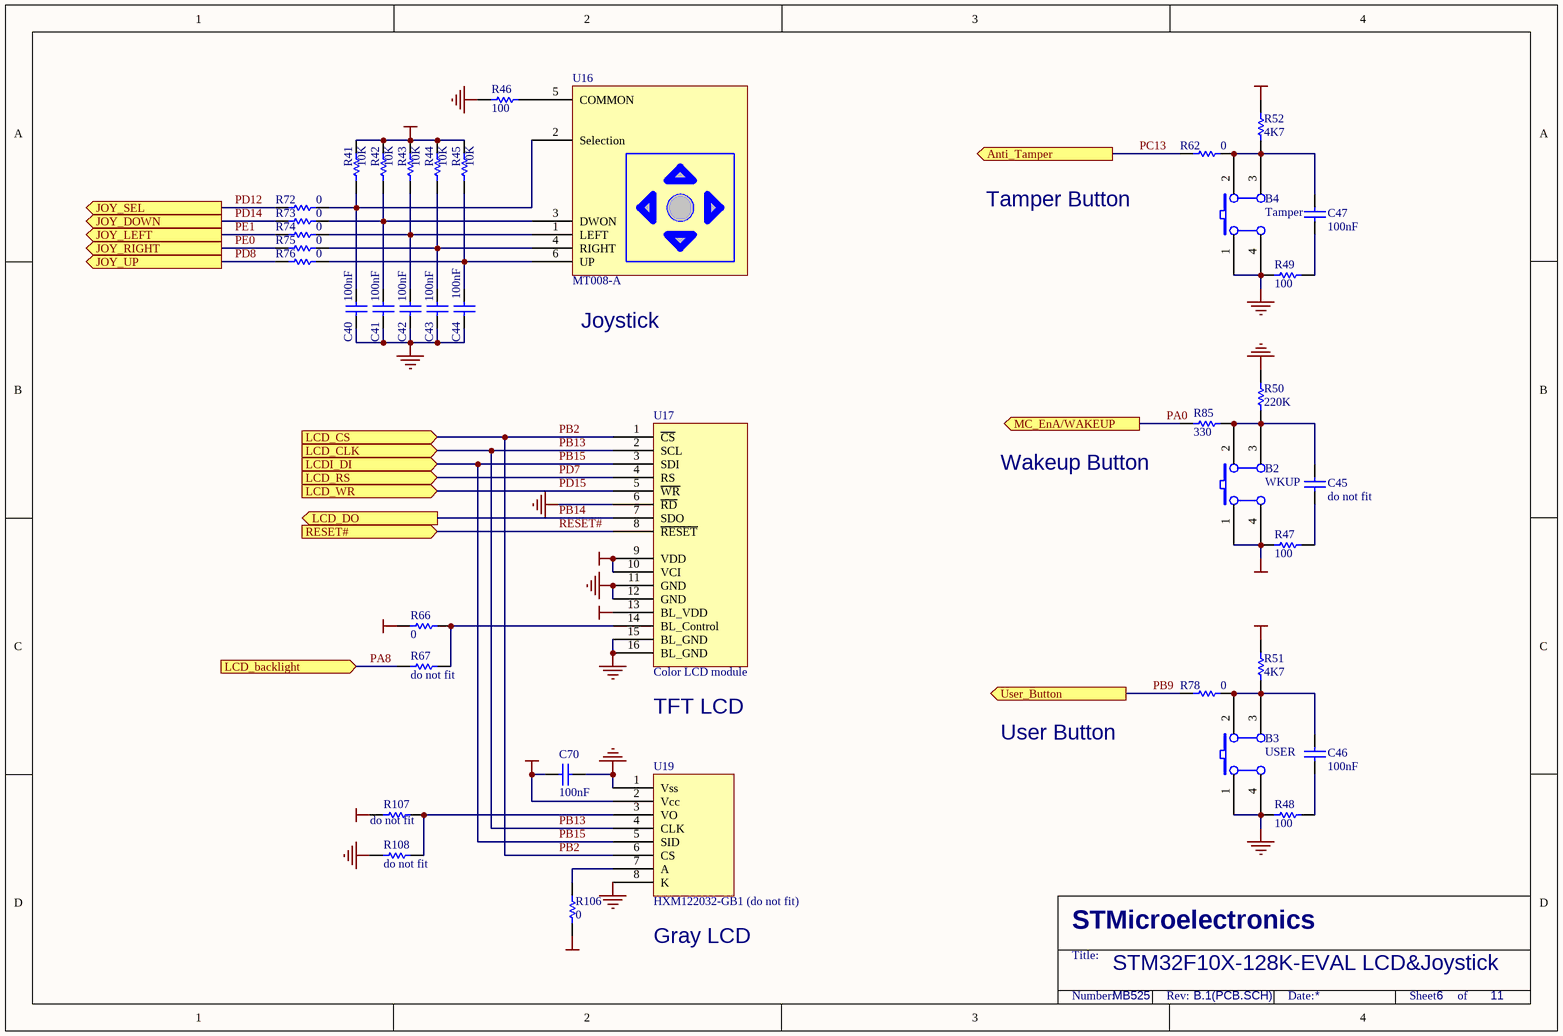
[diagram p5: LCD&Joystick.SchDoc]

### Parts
B2  WKUP  [PB10]
B3  USER  [PB10]
B4  Tamper  [PB10]
C40  100nF  [0603P]
C41  100nF  [0603P]
C42  100nF  [0603P]
C43  100nF  [0603P]
C44  100nF  [0603P]
C45  do not fit  [0603P]
C46  100nF  [0603P]
C47  100nF  [0603P]
C70  100nF  [0603P]
R41  10K  [0603]
R42  10K  [0603]
R43  10K  [0603]
R44  10K  [0603]
R45  10K  [0603]
R46  100  [0603]
R47  100  [0603]
R48  100  [0603]
R49  100  [0603]
R50  220K  [0603]
R51  4K7  [0603]
R52  4K7  [0603]
R62  0  [0805]
R66  0  [0603]
R67  do not fit  [0603]
R72  0  [0805]
R73  0  [0805]
R74  0  [0805]
R75  0  [0805]
R76  0  [0805]
R78  0  [0805]
R85  330  [0805]
R106  0  [0603]
R107  do not fit  [0603]
R108  do not fit  [0603]
U16  MT008-A  [JOY]
U17  Color LCD module  [AM240320A]
U19  HXM122032-GB1 (do not fit)  [LCD12232-GB1]

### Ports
Anti_Tamper (out), JOY_DOWN (out), JOY_LEFT (out), JOY_RIGHT (out), JOY_SEL (out), JOY_UP (out), LCD_backlight (in), LCD_CLK (in), LCD_CS (in), LCD_DO (out), LCD_RS (in), LCD_WR (in), LCDI_DI (in), MC_EnA/WAKEUP (out), RESET# (in), User_Button (out)

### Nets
+3V3: B2.1(A0) B2.4(A1) C70.1 R41.1 R42.2 R43.2 R44.2 R45.2 R47.1 R51.2 R52.2 R66.2 R107.2 U17.9(VDD) U17.10(VCI) U17.13(BL_VDD) U19.2(Vcc)
+5V: R106.1
GND: B3.1(A0) B3.4(A1) B4.1(A0) B4.4(A1) C40.1 C41.1 C42.1 C43.1 C44.1 C70.2 R46.1 R48.1 R49.1 R50.2 R108.1 U17.6(~{RD}) U17.11(GND) U17.12(GND) U17.15(BL_GND) U17.16(BL_GND) U19.1(Vss) U19.8(K)
PA0: R85.2 ; port MC_EnA/WAKEUP
PA8: R67.1 ; port LCD_backlight
PB2: U17.1(~{CS}) U19.6(CS) ; port LCD_CS
PB9: R78.2 ; port User_Button
PB13: U17.2(SCL) U19.4(CLK) ; port LCD_CLK
PB14: U17.7(SDO) ; port LCD_DO
PB15: U17.3(SDI) U19.5(SID) ; port LCDI_DI
PC13: R62.2 ; port Anti_Tamper
PD7: U17.4(RS) ; port LCD_RS
PD8: R76.2 ; port JOY_UP
PD12: R72.2 ; port JOY_SEL
PD14: R73.2 ; port JOY_DOWN
PD15: U17.5(~{WR}) ; port LCD_WR
PE0: R75.2 ; port JOY_RIGHT
PE1: R74.2 ; port JOY_LEFT
RESET#: U17.8(~{RESET}) ; port RESET#
NetB2_2: B2.2(B0) B2.3(B1) C45.2 R50.1 R85.1
NetB3_2: B3.2(B0) B3.3(B1) C46.2 R51.1 R78.1
NetB4_2: B4.2(B0) B4.3(B1) C47.2 R52.1 R62.1
NetC40_2: C40.2 R41.2 R72.1 U16.2(Selection)
NetC41_2: C41.2 R42.1 R73.1 U16.3(DWON)
NetC42_2: C42.2 R43.1 R74.1 U16.1(LEFT)
NetC43_2: C43.2 R44.1 R75.1 U16.4(RIGHT)
NetC44_2: C44.2 R45.1 R76.1 U16.6(UP)
NetC45_1: C45.1 R47.2
NetC46_1: C46.1 R48.2
NetC47_1: C47.1 R49.2
NetR46_2: R46.2 U16.5(COMMON)
NetR66_1: R66.1 R67.2 U17.14(BL_Control)
NetR106_2: R106.2 U19.7(A)
NetR107_1: R107.1 R108.2 U19.3(VO)

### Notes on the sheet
- Tamper Button
- (near U16) Joystick
- Wakeup Button
- TFT LCD
- User Button
- (near U19) Gray LCD
- STM32F10X-128K-EVAL LCD&Joystick
- MB525
- 6
- 11

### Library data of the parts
B2-B4 = SW PUSHBUTTON: SE PUSHBUTTON
C40-C47 C70 = CAP: Capacitor; Value: 100pF
R41-R49 R62 R66 R67 R72-R76 R78 R85 R106-R108 = Res1: Resistor; Value: 1K
R50-R52 = res1: Resistor; Value: 1K
U16 = MT-008A
U17 = ColorLCD_module
U19 = HXM122032-GB1

## Sheet MotorCtrl.SchDoc
size A4; Revision: B.1(PCB.SCH)
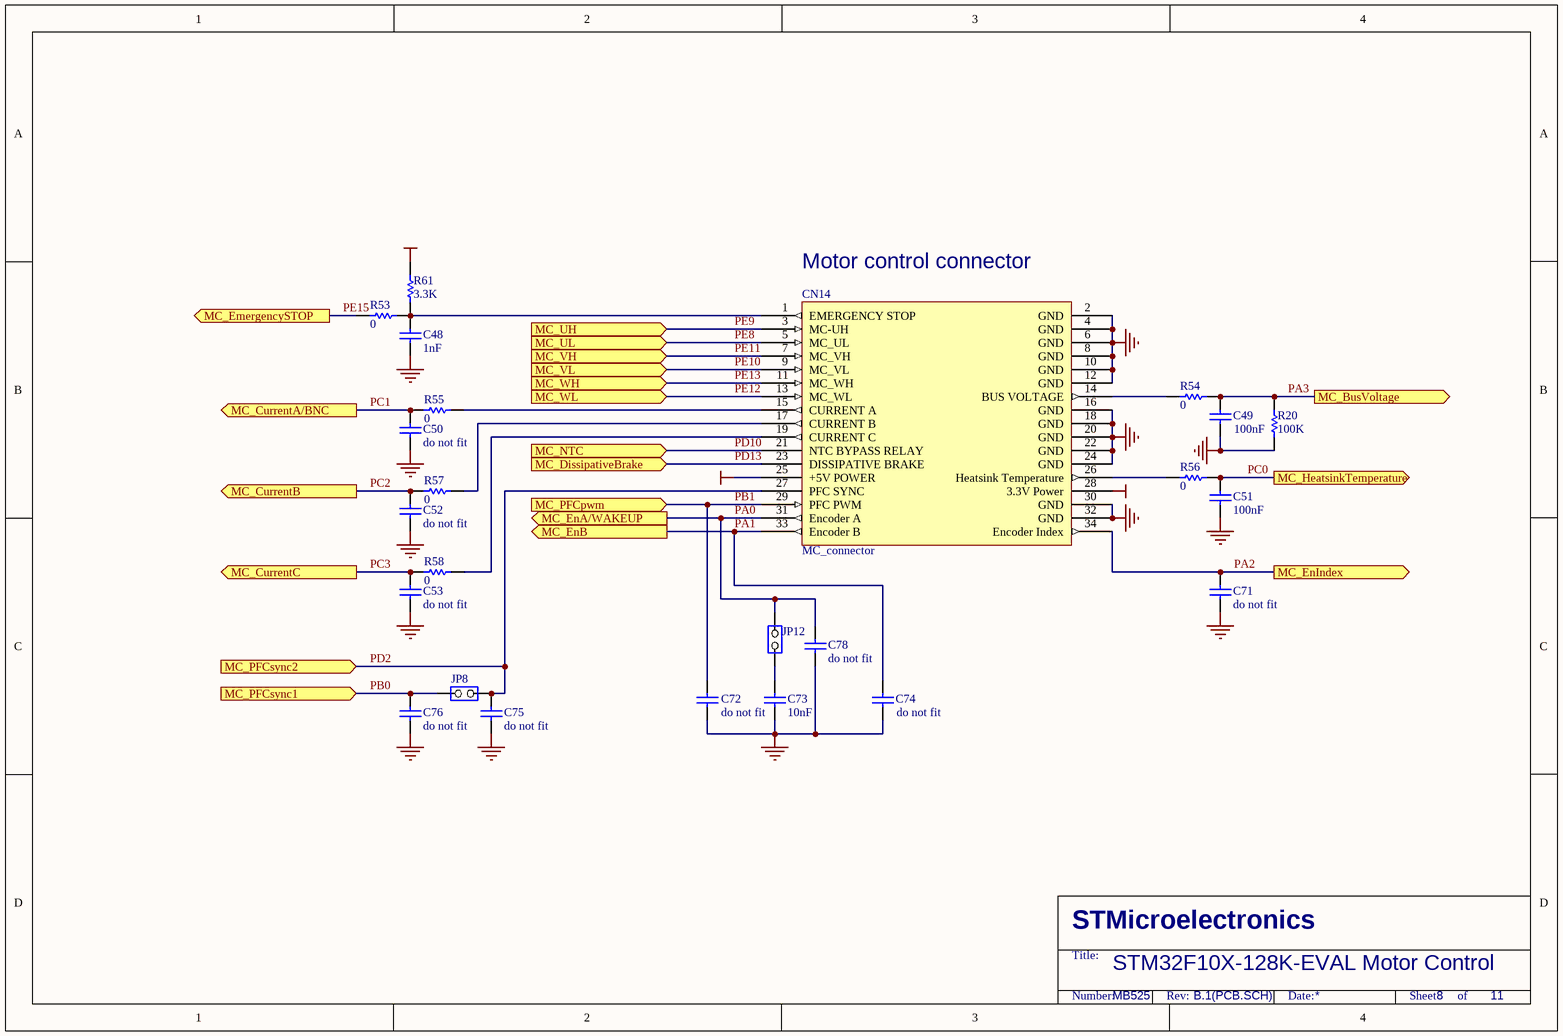
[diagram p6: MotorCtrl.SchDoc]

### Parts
C48  1nF  [0603]
C49  100nF  [0603]
C50  do not fit  [0603]
C51  100nF  [0603]
C52  do not fit  [0603]
C53  do not fit  [0603]
C71  do not fit  [0603]
C72  do not fit  [0603]
C73  10nF  [0603]
C74  do not fit  [0603]
C75  do not fit  [0603]
C76  do not fit  [0603]
C78  do not fit  [0603]
CN14  MC_connector  [IDC34S]
JP8  (no value)  [SIP2]
JP12  (no value)  [SIP2]
R20  100K  [0603]
R53  0  [0805]
R54  0  [0603]
R55  0  [0603]
R56  0  [0603]
R57  0  [0603]
R58  0  [0603]
R61  3.3K  [0603]

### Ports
MC_BusVoltage (out), MC_CurrentA/BNC (out), MC_CurrentB (out), MC_CurrentC (out), MC_DissipativeBrake (in), MC_EmergencySTOP (out), MC_EnA/WAKEUP (out), MC_EnB (out), MC_EnIndex (out), MC_HeatsinkTemperature (out), MC_NTC (in), MC_PFCpwm (in), MC_PFCsync1 (in), MC_PFCsync2 (in), MC_UH (in), MC_UL (in), MC_VH (in), MC_VL (in), MC_WH (in), MC_WL (in)

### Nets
+3V3: CN14.28(3.3V_Power) R61.2
+5V: CN14.25(+5V_POWER)
GND: C48.1 C49.1 C50.1 C51.1 C52.1 C53.1 C71.1 C72.1 C73.1 C74.1 C75.1 C76.1 C78.1 CN14.2(GND) CN14.4(GND) CN14.6(GND) CN14.8(GND) CN14.10(GND) CN14.12(GND) CN14.16(GND) CN14.18(GND) CN14.20(GND) CN14.22(GND) CN14.24(GND) CN14.30(GND) CN14.32(GND) R20.1
PA0: C78.2 CN14.31(Encoder_A) JP12.1(COMMON) ; port MC_EnA/WAKEUP
PA1: C74.2 CN14.33(Encoder_B) ; port MC_EnB
PA2: C71.2 CN14.34(Encoder_Index) ; port MC_EnIndex
PA3: C49.2 R20.2 R54.2 ; port MC_BusVoltage
PB0: C76.2 JP8.2(NO) ; port MC_PFCsync1
PB1: C72.2 CN14.29(PFC_PWM) ; port MC_PFCpwm
PC0: C51.2 R56.2 ; port MC_HeatsinkTemperature
PC1: C50.2 R55.1 ; port MC_CurrentA/BNC
PC2: C52.2 R57.1 ; port MC_CurrentB
PC3: C53.2 R58.1 ; port MC_CurrentC
PD2: C75.2 CN14.27(PFC_SYNC) JP8.1(COMMON) ; port MC_PFCsync2
PD10: CN14.21(NTC_BYPASS_RELAY) ; port MC_NTC
PD13: CN14.23(DISSIPATIVE_BRAKE) ; port MC_DissipativeBrake
PE8: CN14.5(MC_UL) ; port MC_UL
PE9: CN14.3(MC-UH) ; port MC_UH
PE10: CN14.9(MC_VL) ; port MC_VL
PE11: CN14.7(MC_VH) ; port MC_VH
PE12: CN14.13(MC_WL) ; port MC_WL
PE13: CN14.11(MC_WH) ; port MC_WH
PE15: R53.2 ; port MC_EmergencySTOP
NetC48_2: C48.2 CN14.1(EMERGENCY_STOP) R53.1 R61.1
NetC73_2: C73.2 JP12.2(NO)
NetCN14_14: CN14.14(BUS_VOLTAGE) R54.1
NetCN14_15: CN14.15(CURRENT_A) R55.2
NetCN14_17: CN14.17(CURRENT_B) R57.2
NetCN14_19: CN14.19(CURRENT_C) R58.2
NetCN14_26: CN14.26(Heatsink_Temperature) R56.1

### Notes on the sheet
- (near CN14) Motor control connector
- STM32F10X-128K-EVAL Motor Control
- MB525
- 8
- 11

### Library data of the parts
C48 = CAP: Capacitor; Value: 100pF
C49-C53 C71-C76 C78 = cap: Capacitor; Value: 100pF
JP8 JP12 = JP2
R20 R53-R58 R61 = Res1: Resistor; Value: 1K

## Sheet Peripherals.SchDoc
size A4; Revision: B.1(PCB.SCH)
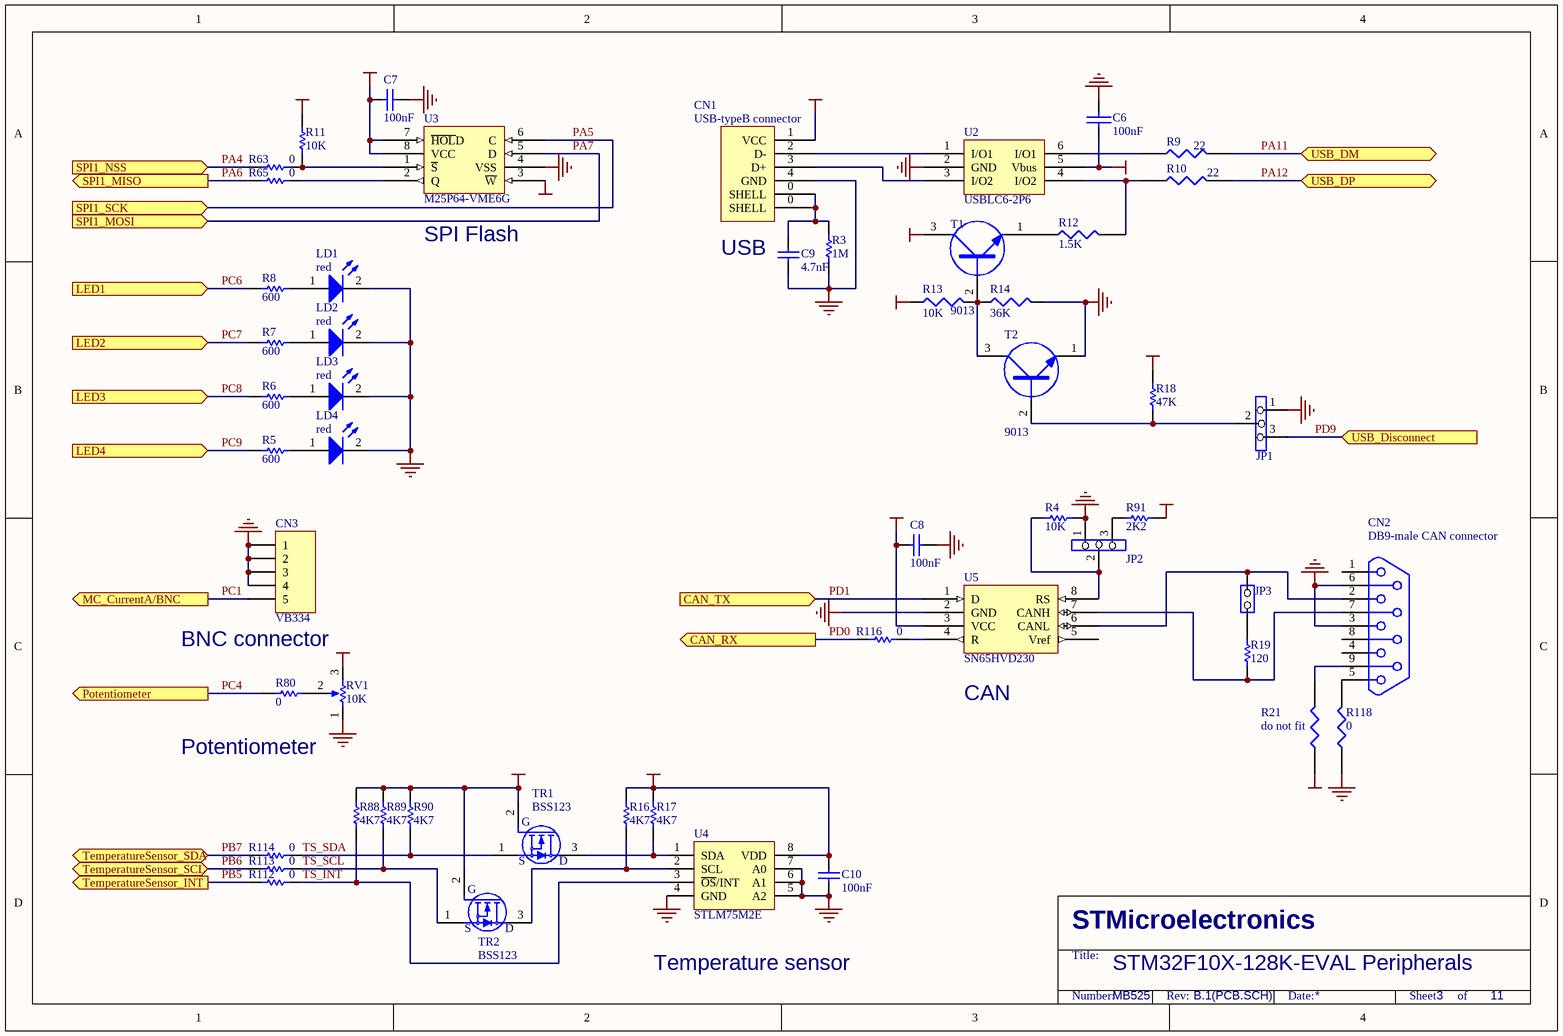
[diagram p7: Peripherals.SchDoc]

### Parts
C6  100nF  [0603P]
C7  100nF  [0603P]
C8  100nF  [0603P]
C9  4.7nF  [0603]
C10  100nF  [0603P]
CN1  USB-typeB connector  [USB-B]
CN2  DB9-male CAN connector  [DB9/M]
CN3  VB334  [VB334]
JP1  (no value)  [SIP3]
JP2  (no value)  [SIP3]
JP3  (no value)  [SIP2]
LD1  red  [D0603]
LD2  red  [D0603]
LD3  red  [D0603]
LD4  red  [D0603]
R3  1M  [0603]
R4  10K  [0603]
R5  600  [0805]
R6  600  [0805]
R7  600  [0805]
R8  600  [0805]
R9  22  [0603]
R10  22  [0603]
R11  10K  [0603]
R12  1.5K  [0603]
R13  10K  [0603]
R14  36K  [0603]
R16  4K7  [0603]
R17  4K7  [0603]
R18  47K  [0603]
R19  120  [0603]
R21  do not fit  [0603]
R63  0  [0805]
R65  0  [0805]
R80  0  [0805]
R88  4K7  [0603]
R89  4K7  [0603]
R90  4K7  [0603]
R91  2K2  [0603]
R112  0  [0805]
R113  0  [0805]
R114  0  [0805]
R116  0  [0805]
R118  0  [0603]
RV1  10K  [ADJRH]
T1  9013  [SOT-23]
T2  9013  [SOT-23]
TR1  BSS123  [SOT-23]
TR2  BSS123  [SOT-23]
U2  USBLC6-2P6  [SOT-666]
U3  M25P64-VME6G  [VDFPN8(8*6)]
U4  STLM75M2E  [SO8]
U5  SN65HVD230  [SO8]

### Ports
CAN_RX (out), CAN_TX (in), LED1 (in), LED2 (in), LED3 (in), LED4 (in), MC_CurrentA/BNC (out), Potentiometer (out), SPI1_MISO (out), SPI1_MOSI (in), SPI1_NSS (in), SPI1_SCK (in), TemperatureSensor_INT (out), TemperatureSensor_SCL (bidir), TemperatureSensor_SDA (bidir), USB_Disconnect (in), USB_DM (bidir), USB_DP (bidir)

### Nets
+3V3: C7.2 C8.2 R11.2 R18.2 R21.1 R88.2 R89.2 R90.2 R91.2 RV1.3(TOP) T1.3(C) TR1.2(G) TR2.2(G) U3.3(~{W}) U3.7(~{HOL}D) U3.8(VCC) U5.3(VCC)
+5V: C10.2 R16.2 R17.2 U4.8(VDD)
GND: C6.1 C7.1 C8.1 C9.1 C10.1 CN1.4(GND) CN2.3 CN2.6 CN3.1 CN3.2 CN3.3 CN3.4 JP1.1 JP2.1 LD1.2(K) LD2.2(K) LD3.2(K) LD4.2(K) R3.1 R4.2 R14.2 R118.1 RV1.1(BOT) T2.1(E) U2.2(GND) U3.4(VSS) U4.4(GND) U4.5(A2) U4.6(A1) U4.7(A0) U5.2(GND)
U5V: C6.2 CN1.1(VCC) R13.1 U2.5(Vbus)
PA4: R63.2 ; port SPI1_NSS
PA5: U3.6(C) ; port SPI1_SCK
PA6: R65.1 ; port SPI1_MISO
PA7: U3.5(D) ; port SPI1_MOSI
PA11: R9.2 ; port USB_DM
PA12: R10.2 ; port USB_DP
PB5: R112.2 ; port TemperatureSensor_INT
PB6: R113.2 ; port TemperatureSensor_SCL
PB7: R114.2 ; port TemperatureSensor_SDA
PC1: CN3.5 ; port MC_CurrentA/BNC
PC4: R80.1 ; port Potentiometer
PC6: R8.2 ; port LED1
PC7: R7.2 ; port LED2
PC8: R6.2 ; port LED3
PC9: R5.2 ; port LED4
PD0: R116.2 ; port CAN_RX
PD1: U5.1(D) ; port CAN_TX
PD9: JP1.3 ; port USB_Disconnect
TS_INT: R88.1 R112.1 U4.3(~{OS}/INT)
TS_SCL: R89.1 R113.1 TR2.1(S)
TS_SDA: R90.1 R114.1 TR1.1(S)
NetC9_2: C9.2 CN1.0(SHELL) R3.2
NetCN1_2: CN1.2(D-) U2.1(I/O1)
NetCN1_3: CN1.3(D+) U2.3(I/O2)
NetCN2_2: CN2.2 JP3.2(NO) U5.6(CANL)
NetCN2_5: CN2.5 R118.2
NetCN2_7: CN2.7 R19.1 U5.7(CANH)
NetCN2_9: CN2.9 R21.2
NetJP1_2: JP1.2 R18.1 T2.2(B)
NetJP2_2: JP2.2 R4.1 U5.8(RS)
NetJP2_3: JP2.3 R91.1
NetJP3_1: JP3.1(COMMON) R19.2
NetLD1_1: LD1.1(A) R8.1
NetLD2_1: LD2.1(A) R7.1
NetLD3_1: LD3.1(A) R6.1
NetLD4_1: LD4.1(A) R5.1
NetR9_1: R9.1 U2.6(I/O1)
NetR10_1: R10.1 R12.2 U2.4(I/O2)
NetR11_1: R11.1 R63.1 U3.1(~{S})
NetR12_1: R12.1 T1.1(E)
NetR13_2: R13.2 R14.1 T1.2(B) T2.3(C)
NetR16_1: R16.1 TR2.3(D) U4.2(SCL)
NetR17_1: R17.1 TR1.3(D) U4.1(SDA)
NetR65_2: R65.2 U3.2(Q)
NetR80_2: R80.2 RV1.2(TAP)
NetR116_1: R116.1 U5.4(R)

Not connected (* = marked no-connect by the designer): CN2 1 4 8; U5 5(Vref)

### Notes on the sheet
- (near U3) SPI Flash
- USB
- BNC connector
- (near U5) CAN
- Potentiometer
- Temperature sensor
- STM32F10X-128K-EVAL Peripherals
- MB525
- 3
- 11

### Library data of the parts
C6-C8 = CAP: Capacitor
C9 = CAP: Capacitor; Value: 100pF
C10 = cap: Capacitor; Value: 100pF
CN1 = USB-B
CN2 = DB9
CN3 = Header 5: Header, 5-Pin
JP1 JP2 = Jumper3
JP3 = JP2
LD1-LD4 = LED2: Typical RED, GREEN, YELLOW, AMBER GaAs LED
R3 R5-R8 R11 R16-R18 R63 R65 R80 R88-R90 R112-R114 R116 = Res1: Resistor; Value: 1K
R4 R19 R91 = res1: Resistor; Value: 1K
R9 R10 R12 R21 R118 = RES1
R13 R14 = R: Right: 20; Bottom: 30
RV1 = RV
T1 T2 = NPN
TR1 TR2 = 2N7000
U2 = USBLC6-2
U4 = STLM75DW2F
U5 = SN65HVD230D

## Sheet Power.SchDoc
size A4; Revision: B.1(PCB.SCH)
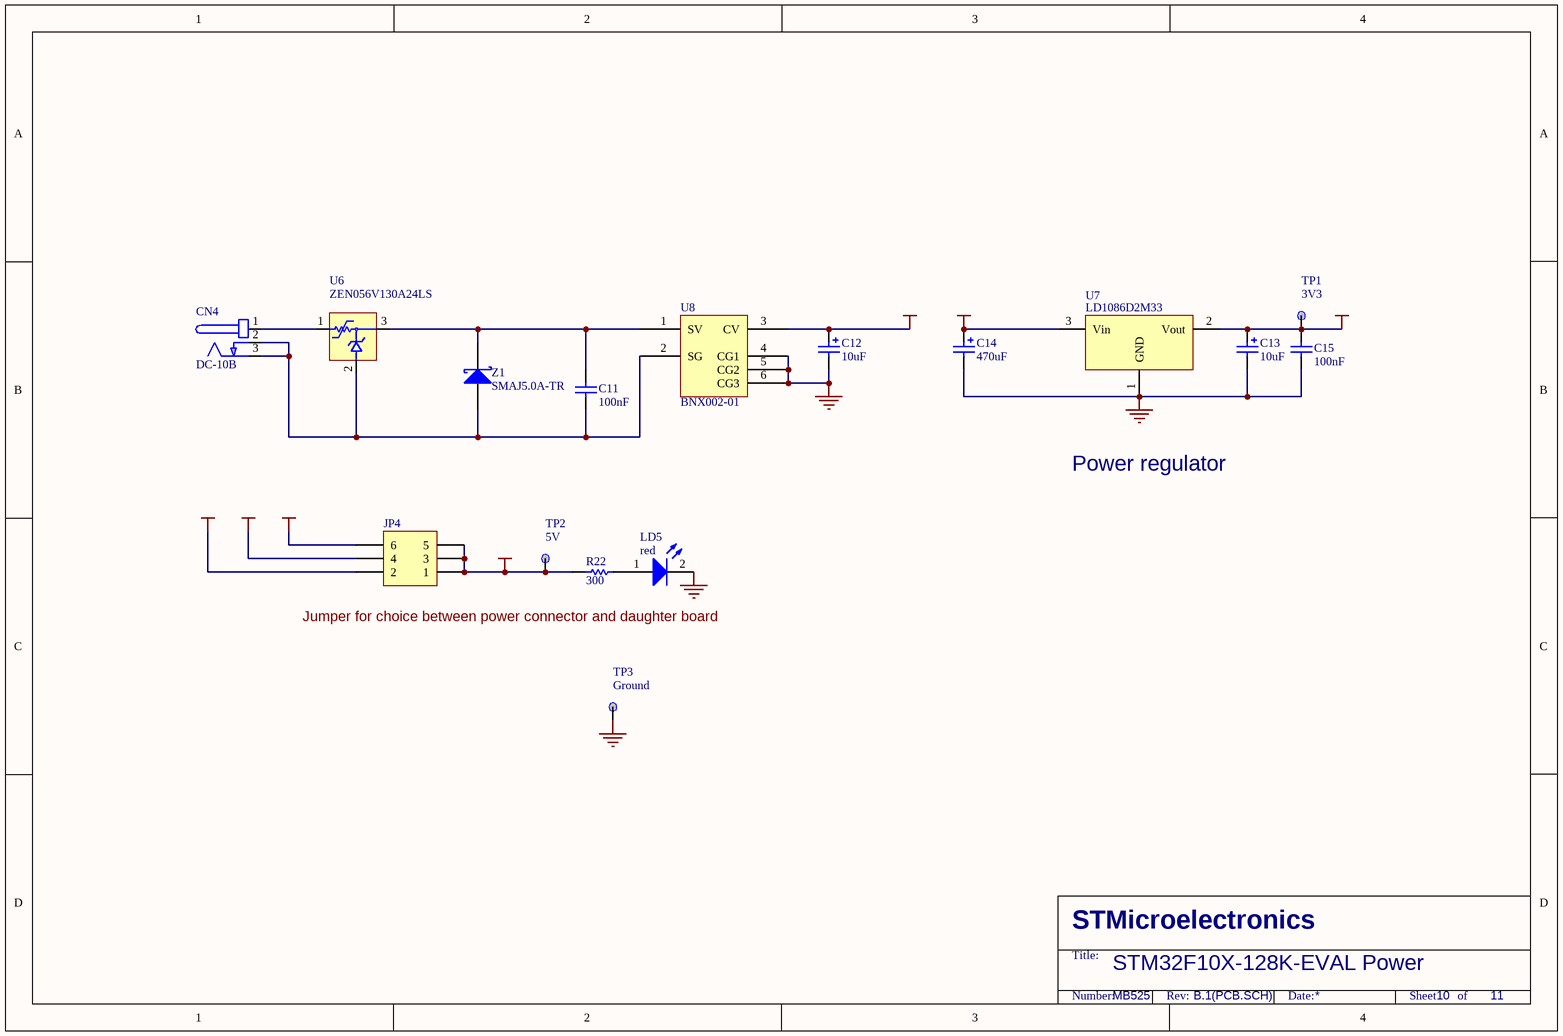
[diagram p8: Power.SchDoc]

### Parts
C11  100nF  [0603P]
C12  10uF  [C160M]
C13  10uF  [TAN-B]
C14  470uF  [C310M]
C15  100nF  [0603P]
CN4  DC-10B  [DC10B]
JP4  (no value)  [2*3P]
LD5  red  [D0603]
R22  300  [0603]
TP1  3V3  [TP]
TP2  5V  [TP]
TP3  Ground  [TP]
U6  ZEN056V130A24LS  [polyzen]
U7  LD1086D2M33  [D2PAK/A]
U8  BNX002-01  [BNX001]
Z1  SMAJ5.0A-TR  [1R1C]

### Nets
+3V3: C13.1 C15.1 TP1.1 U7.2(Vout)
+5V: C14.1 JP4.1 JP4.3 JP4.5 R22.2 TP2.1 U7.3(Vin)
D5V: JP4.4
E5V: C12.1 JP4.6 U8.3(CV)
GND: C12.2 C13.2 C14.2 C15.2 LD5.2(K) TP3.1 U7.1(GND) U8.4(CG1) U8.5(CG2) U8.6(CG3)
U5V: JP4.2
NetC11_1: C11.1 U6.3 U8.1(SV) Z1.2(K)
NetC11_2: C11.2 CN4.2(GND) CN4.3(GND) U6.2 U8.2(SG) Z1.1(A)
NetCN4_1: CN4.1(+) U6.1
NetLD5_1: LD5.1(A) R22.1

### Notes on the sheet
- Power regulator
- Jumper for choice between power connector and daughter board
- STM32F10X-128K-EVAL Power
- MB525
- 10
- 11

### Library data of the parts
C11 = CAP: Capacitor; Value: 100pF
C12 = Cap Pol1: Polarized Capacitor (Radial); Value: 47uF
C13 = Cap Pol1: Polarized Capacitor (Radial)
C14 = Cap Pol1: Polarized Capacitor (Radial); Value: 10uF
C15 = Cap: Capacitor; Value: 10nF
CN4 = PJ202A
JP4 = Header 3X2: Header, 3-Pin, Dual row
LD5 = LED2: as LD1 on sheet Peripherals
R22 = res1: Resistor; Value: 1K
TP1-TP3 = TP
U7 = VOLTREG1
U8 = BNX002
Z1 = D Schottky: Schottky Diode; Code - JEDEC: DO-214-AA

## Sheet RS232&IrDA.SchDoc
size A4; Revision: B.1(PCB.SCH)
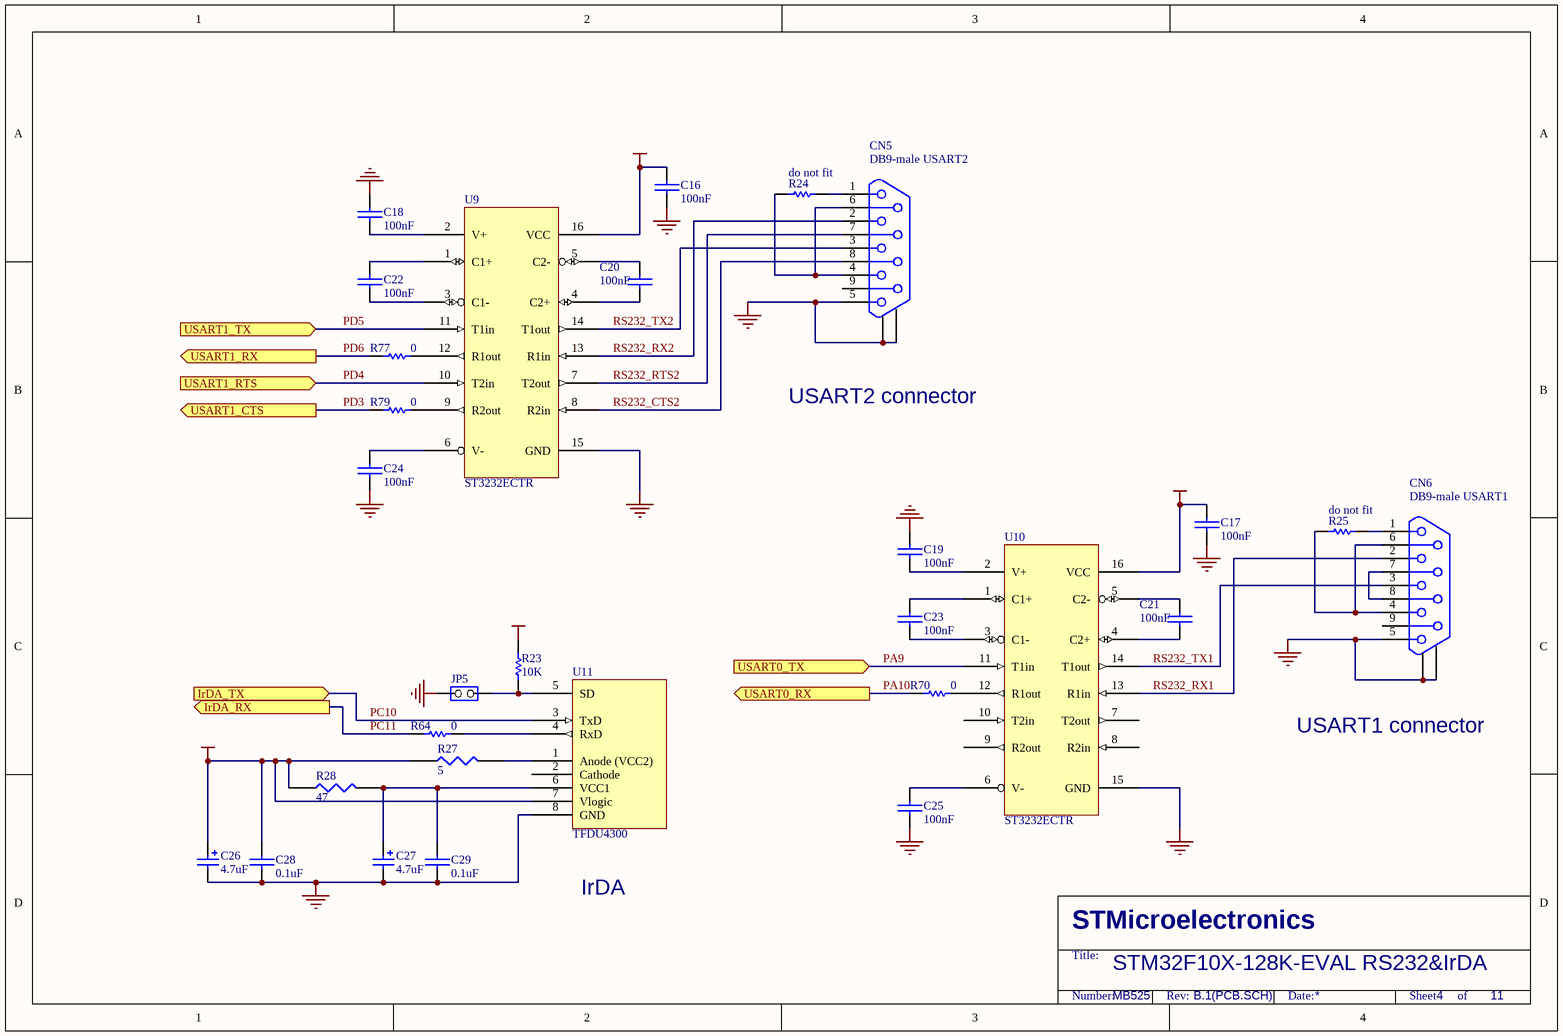
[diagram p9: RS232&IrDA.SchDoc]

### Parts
C16  100nF  [0603P]
C17  100nF  [0603P]
C18  100nF  [0603P]
C19  100nF  [0603P]
C20  100nF  [0603P]
C21  100nF  [0603P]
C22  100nF  [0603P]
C23  100nF  [0603P]
C24  100nF  [0603P]
C25  100nF  [0603P]
C26  4.7uF  [TAN-B]
C27  4.7uF  [TAN-B]
C28  0.1uF  [0603P]
C29  0.1uF  [0603P]
CN5  DB9-male USART2  [DB9/M]
CN6  DB9-male USART1  [DB9/M]
JP5  (no value)  [SIP2]
R23  10K  [0603]
R24  do not fit  [0603_NC]
R25  do not fit  [0603_NC]
R27  5  [0603]
R28  47  [0603]
R64  0  [0805]
R70  0  [0805]
R77  0  [0805]
R79  0  [0805]
U9  ST3232ECTR  [TSSOP16]
U10  ST3232ECTR  [TSSOP16]
U11  TFDU4300  [IR_VISHAY3]

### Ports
IrDA_RX (out), IrDA_TX (in), USART0_RX (out), USART0_TX (in), USART1_CTS (out), USART1_RTS (in), USART1_RX (out), USART1_TX (in)

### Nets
+3V3: C16.1 C17.1 C26.1 C28.1 R23.2 R27.1 R28.1 U9.16(VCC) U10.16(VCC) U11.7(Vlogic)
GND: C16.2 C17.2 C18.1 C19.1 C24.1 C25.1 C26.2 C27.2 C28.2 C29.2 CN5.0 CN5.5 CN6.0 CN6.5 JP5.2(NO) U9.15(GND) U10.15(GND) U11.8(GND)
PA9: U10.11(T1in) ; port USART0_TX
PA10: R70.2 ; port USART0_RX
PC10: U11.3(TxD) ; port IrDA_TX
PC11: R64.2 ; port IrDA_RX
PD3: R79.2 ; port USART1_CTS
PD4: U9.10(T2in) ; port USART1_RTS
PD5: U9.11(T1in) ; port USART1_TX
PD6: R77.2 ; port USART1_RX
RS232_CTS2: CN5.8 U9.8(R2in)
RS232_RTS2: CN5.7 U9.7(T2out)
RS232_RX1: CN6.2 U10.13(R1in)
RS232_RX2: CN5.2 U9.13(R1in)
RS232_TX1: CN6.3 U10.14(T1out)
RS232_TX2: CN5.3 U9.14(T1out)
NetC18_2: C18.2 U9.2(V+)
NetC19_2: C19.2 U10.2(V+)
NetC20_1: C20.1 U9.4(C2+)
NetC20_2: C20.2 U9.5(C2-)
NetC21_1: C21.1 U10.4(C2+)
NetC21_2: C21.2 U10.5(C2-)
NetC22_1: C22.1 U9.1(C1+)
NetC22_2: C22.2 U9.3(C1-)
NetC23_1: C23.1 U10.1(C1+)
NetC23_2: C23.2 U10.3(C1-)
NetC24_2: C24.2 U9.6(V-)
NetC25_2: C25.2 U10.6(V-)
NetC27_1: C27.1 C29.1 R28.2 U11.6(VCC1)
NetCN5_1: CN5.1 R24.2
NetCN5_4: CN5.4 CN5.6 R24.1
NetCN6_1: CN6.1 R25.2
NetCN6_4: CN6.4 CN6.6 R25.1
NetCN6_7: CN6.7 CN6.8
NetJP5_1: JP5.1(COMMON) R23.1 U11.5(SD)
NetR27_2: R27.2 U11.1(Anode_(VCC2))
NetR64_1: R64.1 U11.4(RxD)
NetR70_1: R70.1 U10.12(R1out)
NetR77_1: R77.1 U9.12(R1out)
NetR79_1: R79.1 U9.9(R2out)

Not connected (* = marked no-connect by the designer): CN5 9; CN6 9; U10 7(T2out) 8(R2in) 9(R2out) 10(T2in); U11 2(Cathode)

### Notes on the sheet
- USART2 connector
- USART1 connector
- IrDA
- STM32F10X-128K-EVAL RS232&IrDA
- MB525
- 4
- 11

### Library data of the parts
C16-C25 C28 C29 = CAP: Capacitor
C26 C27 = Cap Pol1: as C34 on sheet Audio
CN5 CN6 = DB9
JP5 = JP2
R23 R64 R70 R77 R79 = Res1: Resistor; Value: 1K
R24 R25 = res1: Resistor; Value: 1K
R27 R28 = RES1
U9 U10 = ST3232: 3.3V/5V Dual RS232 Transceiver w/ Int. Cap.

## Sheet SD&Smart Card.SchDoc
size A4; Revision: B.1(PCB.SCH)
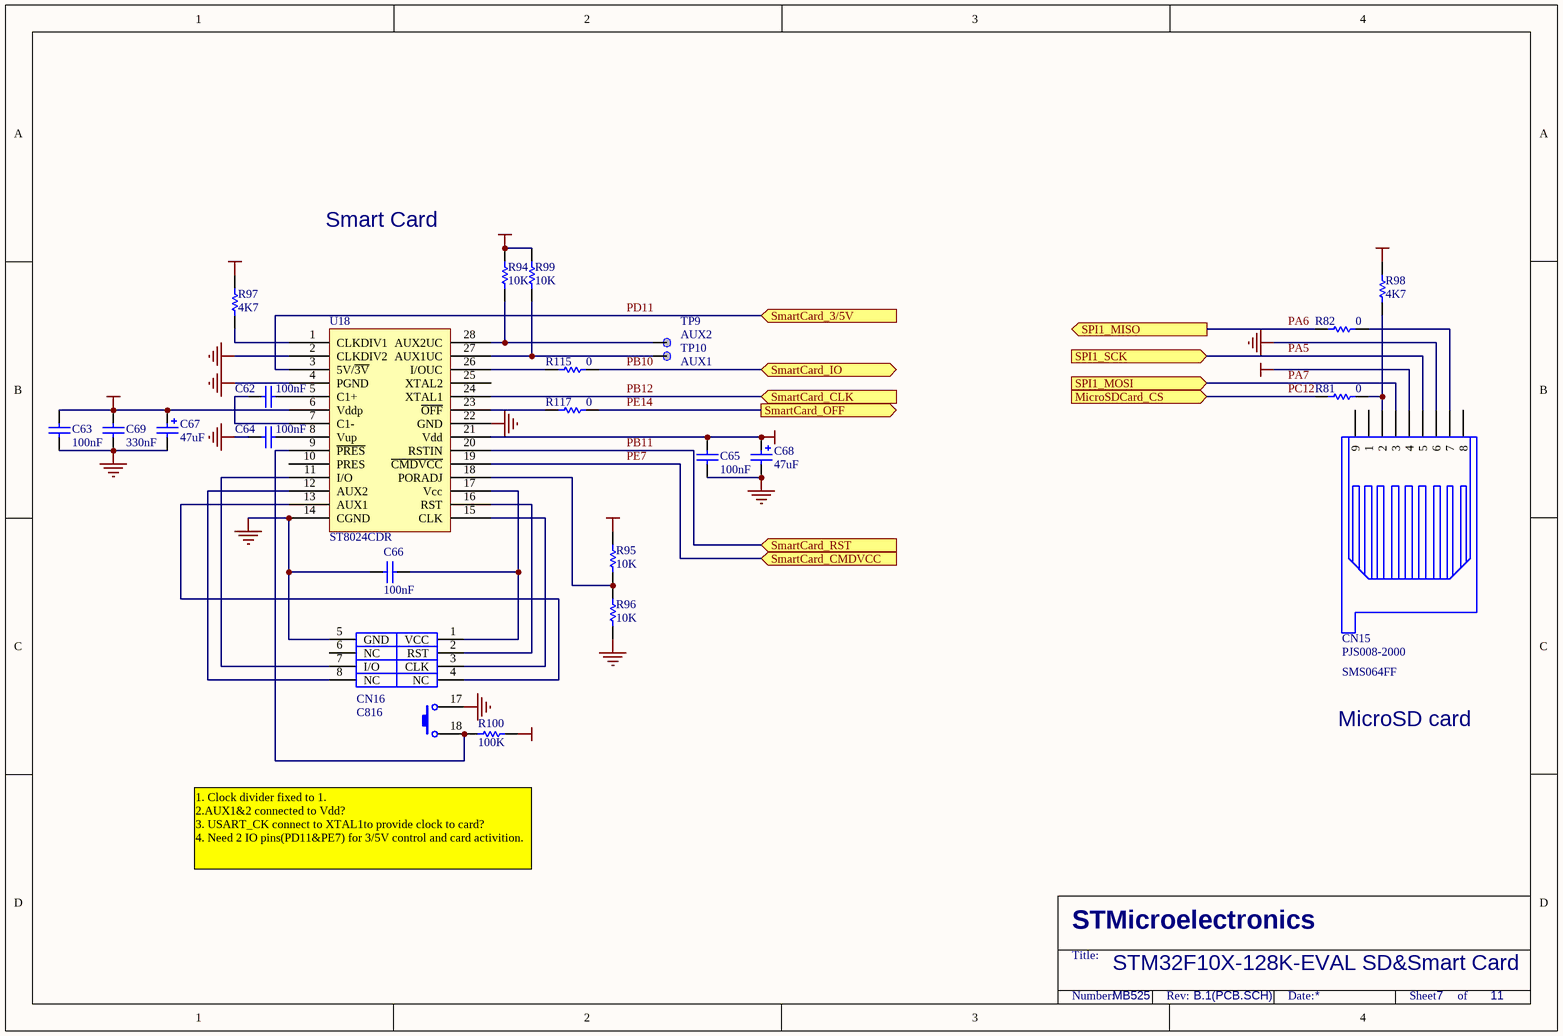
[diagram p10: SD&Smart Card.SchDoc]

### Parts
C62  100nF  [0603P]
C63  100nF  [0603P]
C64  100nF  [0603P]
C65  100nF  [0603P]
C66  100nF  [0603P]
C67  47uF  [TAN-B]
C68  47uF  [TAN-B]
C69  330nF  [0603]
CN15  PJS008-2000  [MSD(PJS008)]
CN16  C816  [SAM(C816)]
R81  0  [0805]
R82  0  [0805]
R94  10K  [0603]
R95  10K  [0603]
R96  10K  [0603]
R97  4K7  [0603]
R98  4K7  [0603]
R99  10K  [0603]
R100  100K  [0603]
R115  0  [0805]
R117  0  [0805]
TP9  AUX2  [TP]
TP10  AUX1  [TP]
U18  ST8024CDR  [SO28]

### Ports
MicroSDCard_CS (in), SmartCard_3/5V (in), SmartCard_CLK (in), SmartCard_CMDVCC (in), SmartCard_IO (bidir), SmartCard_OFF (out), SmartCard_RST (in), SPI1_MISO (out), SPI1_MOSI (in), SPI1_SCK (in)

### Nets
+3V3: C65.1 C68.1 CN15.4 R94.1 R95.1 R97.1 R98.2 R99.1 R100.1 U18.21(Vdd)
+5V: C63.1 C67.1 C69.1 U18.6(Vddp)
GND: C63.2 C64.2 C65.2 C66.1 C67.2 C68.2 C69.2 CN15.6 CN16.5(GND) CN16.17 R96.2 U18.2(CLKDIV2) U18.4(PGND) U18.14(CGND) U18.22(GND)
PA5: CN15.5 ; port SPI1_SCK
PA6: R82.1 ; port SPI1_MISO
PA7: CN15.3 ; port SPI1_MOSI
PB10: R115.2 ; port SmartCard_IO
PB11: U18.20(RSTIN) ; port SmartCard_RST
PB12: U18.24(XTAL1) ; port SmartCard_CLK
PC12: R81.2 ; port MicroSDCard_CS
PD11: U18.3(5V/~{3V}) ; port SmartCard_3/5V
PE7: U18.19(~{CMDVCC}) ; port SmartCard_CMDVCC
PE14: R117.1 ; port SmartCard_OFF
NetC62_1: C62.1 U18.7(C1-)
NetC62_2: C62.2 U18.5(C1+)
NetC64_1: C64.1 U18.8(Vup)
NetC66_2: C66.2 CN16.1(VCC) U18.17(Vcc)
NetCN15_2: CN15.2 R81.1 R98.1
NetCN15_7: CN15.7 R82.2
NetCN16_2: CN16.2(RST) U18.16(RST)
NetCN16_3: CN16.3(CLK) U18.15(CLK)
NetCN16_4: CN16.4(NC) U18.13(AUX1)
NetCN16_7: CN16.7(I/O) U18.11(I/O)
NetCN16_8: CN16.8(NC) U18.12(AUX2)
NetCN16_18: CN16.18 R100.2 U18.9(~{PRES})
NetR94_2: R94.2 TP9.1 U18.28(AUX2UC)
NetR95_2: R95.2 R96.1 U18.18(PORADJ)
NetR97_2: R97.2 U18.1(CLKDIV1)
NetR99_2: R99.2 TP10.1 U18.27(AUX1UC)
NetR115_1: R115.1 U18.26(I/OUC)
NetR117_2: R117.2 U18.23(~{OFF})

Not connected (* = marked no-connect by the designer): CN15 1 8 9; CN16 6(NC); U18 10(PRES) 25(XTAL2)

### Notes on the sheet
- Smart Card
- SMS064FF
- MicroSD card
- 1. Clock divider fixed to 1.
  2.AUX1&2 connected to Vdd?
  3. USART_CK connect to XTAL1to provide clock to card?
  4. Need 2 IO pins(PD11&PE7) for 3/5V control and card activition.
- STM32F10X-128K-EVAL SD&Smart Card
- MB525
- 7
- 11

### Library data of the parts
C62-C66 = CAP: Capacitor
C67 C68 = Cap Pol1: as C34 on sheet Audio
C69 = CAP: Capacitor; Value: 100nF
CN15 = SMS016AFA5E
CN16 = Smart_card_CN
R81 R82 R94-R100 R115 R117 = Res1: Resistor; Value: 1K
TP9 TP10 = TP
U18 = ST8024CTR

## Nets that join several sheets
+3V3: MCU (5 pins), Audio (7 pins), Extension (CN12.48), JTAG&SWD (9 pins), LCD&Joystick (17 pins), MotorCtrl (CN14.28 R61.2), Peripherals (17 pins), Power (C13.1 C15.1 TP1.1 U7.2), RS232&IrDA (10 pins), SD&Smart Card (10 pins)
+5V: LCD&Joystick (R106.1), MotorCtrl (CN14.25), Peripherals (C10.2 R16.2 R17.2 U4.8), Power (7 pins), SD&Smart Card (C63.1 C67.1 C69.1 U18.6)
D5V: Extension (CN12.49 CN13.19), Power (JP4.4)
GND: MCU (29 pins), Audio (13 pins), Extension (11 pins), JTAG&SWD (26 pins), LCD&Joystick (22 pins), MotorCtrl (27 pins), Peripherals (31 pins), Power (10 pins), RS232&IrDA (18 pins), SD&Smart Card (15 pins)
U5V: Peripherals (C6.2 CN1.1 R13.1 U2.5), Power (JP4.2)
PA0: MCU (U1.23), Extension (CN12.6), LCD&Joystick (R85.2), MotorCtrl (C78.2 CN14.31 JP12.1)
PA1: MCU (U1.24), Extension (CN12.7), MotorCtrl (C74.2 CN14.33)
PA2: MCU (U1.25), Extension (CN12.8), MotorCtrl (C71.2 CN14.34)
PA3: MCU (U1.26), Extension (CN12.9), MotorCtrl (C49.2 R20.2 R54.2)
PA4: MCU (U1.29), Extension (CN12.11), Peripherals (R63.2)
PA5: MCU (U1.30), Extension (CN12.12), Peripherals (U3.6), SD&Smart Card (CN15.5)
PA6: MCU (U1.31), Extension (CN12.13), Peripherals (R65.1), SD&Smart Card (R82.1)
PA7: MCU (U1.32), Extension (CN12.14), Peripherals (U3.5), SD&Smart Card (CN15.3)
PA8: MCU (TP8.1 U1.67), Extension (CN13.45), LCD&Joystick (R67.1)
PA9: MCU (U1.68), Extension (CN13.44), RS232&IrDA (U10.11)
PA10: MCU (U1.69), Extension (CN13.43), RS232&IrDA (R70.2)
PA11: MCU (U1.70), Extension (CN13.42), Peripherals (R9.2)
PA12: MCU (U1.71), Extension (CN13.41), Peripherals (R10.2)
PA13: MCU (U1.72), Extension (CN13.40), JTAG&SWD (CN7.7 CN9.2 CN10.2 R101.1)
PA14: MCU (U1.76), Extension (CN13.37), JTAG&SWD (CN7.9 CN9.4 CN10.4 R102.2)
PA15: MCU (U1.77), Extension (CN13.38), JTAG&SWD (CN7.5 CN9.8 CN10.8 R104.1)
PB0: MCU (U1.35), Extension (CN12.17), MotorCtrl (C76.2 JP8.2)
PB1: MCU (U1.36), Extension (CN12.18), MotorCtrl (C72.2 CN14.29)
PB2: MCU (R86.1 U1.37), Extension (CN12.20), LCD&Joystick (U17.1 U19.6)
PB3: MCU (U1.89), Extension (CN13.22), JTAG&SWD (5 pins)
PB4: MCU (U1.90), Extension (CN13.21), JTAG&SWD (CN7.3 JP10.1 R122.1 R130.2)
PB5: MCU (U1.91), Extension (CN13.20), Peripherals (R112.2)
PB6: MCU (U1.92), Extension (CN13.18), Peripherals (R113.2)
PB7: MCU (U1.93), Extension (CN13.17), Peripherals (R114.2)
PB8: MCU (U1.95), Audio (R32.1), Extension (CN13.16)
PB9: MCU (U1.96), Extension (CN13.15), LCD&Joystick (R78.2)
PB10: MCU (U1.47), Extension (CN12.33), SD&Smart Card (R115.2)
PB11: MCU (U1.48), Extension (CN12.34), SD&Smart Card (U18.20)
PB12: MCU (U1.51), Extension (CN12.36), SD&Smart Card (U18.24)
PB13: MCU (U1.52), Extension (CN12.35), LCD&Joystick (U17.2 U19.4)
PB14: MCU (U1.53), Extension (CN12.38), LCD&Joystick (U17.7)
PB15: MCU (U1.54), Extension (CN12.37), LCD&Joystick (U17.3 U19.5)
PC0: MCU (U1.15), Extension (CN12.2), MotorCtrl (C51.2 R56.2)
PC1: MCU (U1.16), Extension (CN12.3), MotorCtrl (C50.2 R55.1), Peripherals (CN3.5)
PC2: MCU (U1.17), Extension (CN12.4), MotorCtrl (C52.2 R57.1)
PC3: MCU (U1.18), Extension (CN12.5), MotorCtrl (C53.2 R58.1)
PC4: MCU (U1.33), Extension (CN12.15), Peripherals (R80.1)
PC5: MCU (U1.34), Audio (R71.1), Extension (CN12.16)
PC6: MCU (U1.63), Extension (CN13.49), Peripherals (R8.2)
PC7: MCU (U1.64), Extension (CN13.48), Peripherals (R7.2)
PC8: MCU (U1.65), Extension (CN13.47), Peripherals (R6.2)
PC9: MCU (U1.66), Extension (CN13.46), Peripherals (R5.2)
PC10: MCU (U1.78), Extension (CN13.35), RS232&IrDA (U11.3)
PC11: MCU (U1.79), Extension (CN13.36), RS232&IrDA (R64.2)
PC12: MCU (U1.80), Extension (CN13.33), SD&Smart Card (R81.2)
PC13: MCU (U1.7), Extension (CN13.4 R59.1), LCD&Joystick (R62.2)
PD0: MCU (U1.81), Extension (CN13.34), Peripherals (R116.2)
PD1: MCU (U1.82), Extension (CN13.31), Peripherals (U5.1)
PD2: MCU (U1.83), Extension (CN13.32), MotorCtrl (C75.2 CN14.27 JP8.1)
PD3: MCU (U1.84), Extension (CN13.29), RS232&IrDA (R79.2)
PD4: MCU (U1.85), Extension (CN13.27), RS232&IrDA (U9.10)
PD5: MCU (U1.86), Extension (CN13.28), RS232&IrDA (U9.11)
PD6: MCU (U1.87), Extension (CN13.25), RS232&IrDA (R77.2)
PD7: MCU (U1.88), Extension (CN13.26), LCD&Joystick (U17.4)
PD8: MCU (U1.55), Extension (CN12.40), LCD&Joystick (R76.2)
PD9: MCU (U1.56), Extension (CN12.41), Peripherals (JP1.3)
PD10: MCU (U1.57), Extension (CN12.42), MotorCtrl (CN14.21)
PD11: MCU (U1.58), Extension (CN12.43), SD&Smart Card (U18.3)
PD12: MCU (U1.59), Extension (CN12.44), LCD&Joystick (R72.2)
PD13: MCU (U1.60), Extension (CN12.45), MotorCtrl (CN14.23)
PD14: MCU (U1.61), Extension (CN12.46), LCD&Joystick (R73.2)
PD15: MCU (U1.62), Extension (CN12.47), LCD&Joystick (U17.5)
PE0: MCU (U1.97), Extension (CN13.14), LCD&Joystick (R75.2)
PE1: MCU (U1.98), Extension (CN13.13), LCD&Joystick (R74.2)
PE2: MCU (U1.1), Extension (CN13.12), JTAG&SWD (CN10.12)
PE3: MCU (U1.2), Extension (CN13.8), JTAG&SWD (R124.2)
PE4: MCU (U1.3), Extension (CN13.7), JTAG&SWD (R125.2)
PE5: MCU (U1.4), Extension (CN13.6), JTAG&SWD (CN10.18)
PE6: MCU (U1.5), Extension (CN13.5), JTAG&SWD (CN10.20)
PE7: MCU (U1.38), Extension (CN12.21), SD&Smart Card (U18.19)
PE8: MCU (U1.39), Extension (CN12.22), MotorCtrl (CN14.5)
PE9: MCU (U1.40), Extension (CN12.23), MotorCtrl (CN14.3)
PE10: MCU (U1.41), Extension (CN12.24), MotorCtrl (CN14.9)
PE11: MCU (U1.42), Extension (CN12.25), MotorCtrl (CN14.7)
PE12: MCU (U1.43), Extension (CN12.26), MotorCtrl (CN14.13)
PE13: MCU (U1.44), Extension (CN12.27), MotorCtrl (CN14.11)
PE14: MCU (U1.45), Extension (CN12.28), SD&Smart Card (R117.1)
PE15: MCU (U1.46), Extension (CN12.29), MotorCtrl (R53.2)
RESET#: MCU (5 pins), Extension (R60.2), JTAG&SWD (CN7.15 CN9.10 CN10.10 JP10.2), LCD&Joystick (U17.8)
